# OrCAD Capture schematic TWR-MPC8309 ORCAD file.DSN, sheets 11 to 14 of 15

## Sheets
11 P10:PCI Interface & Mini PCI: size C; title: PCI Interface and Mini PCI Connector
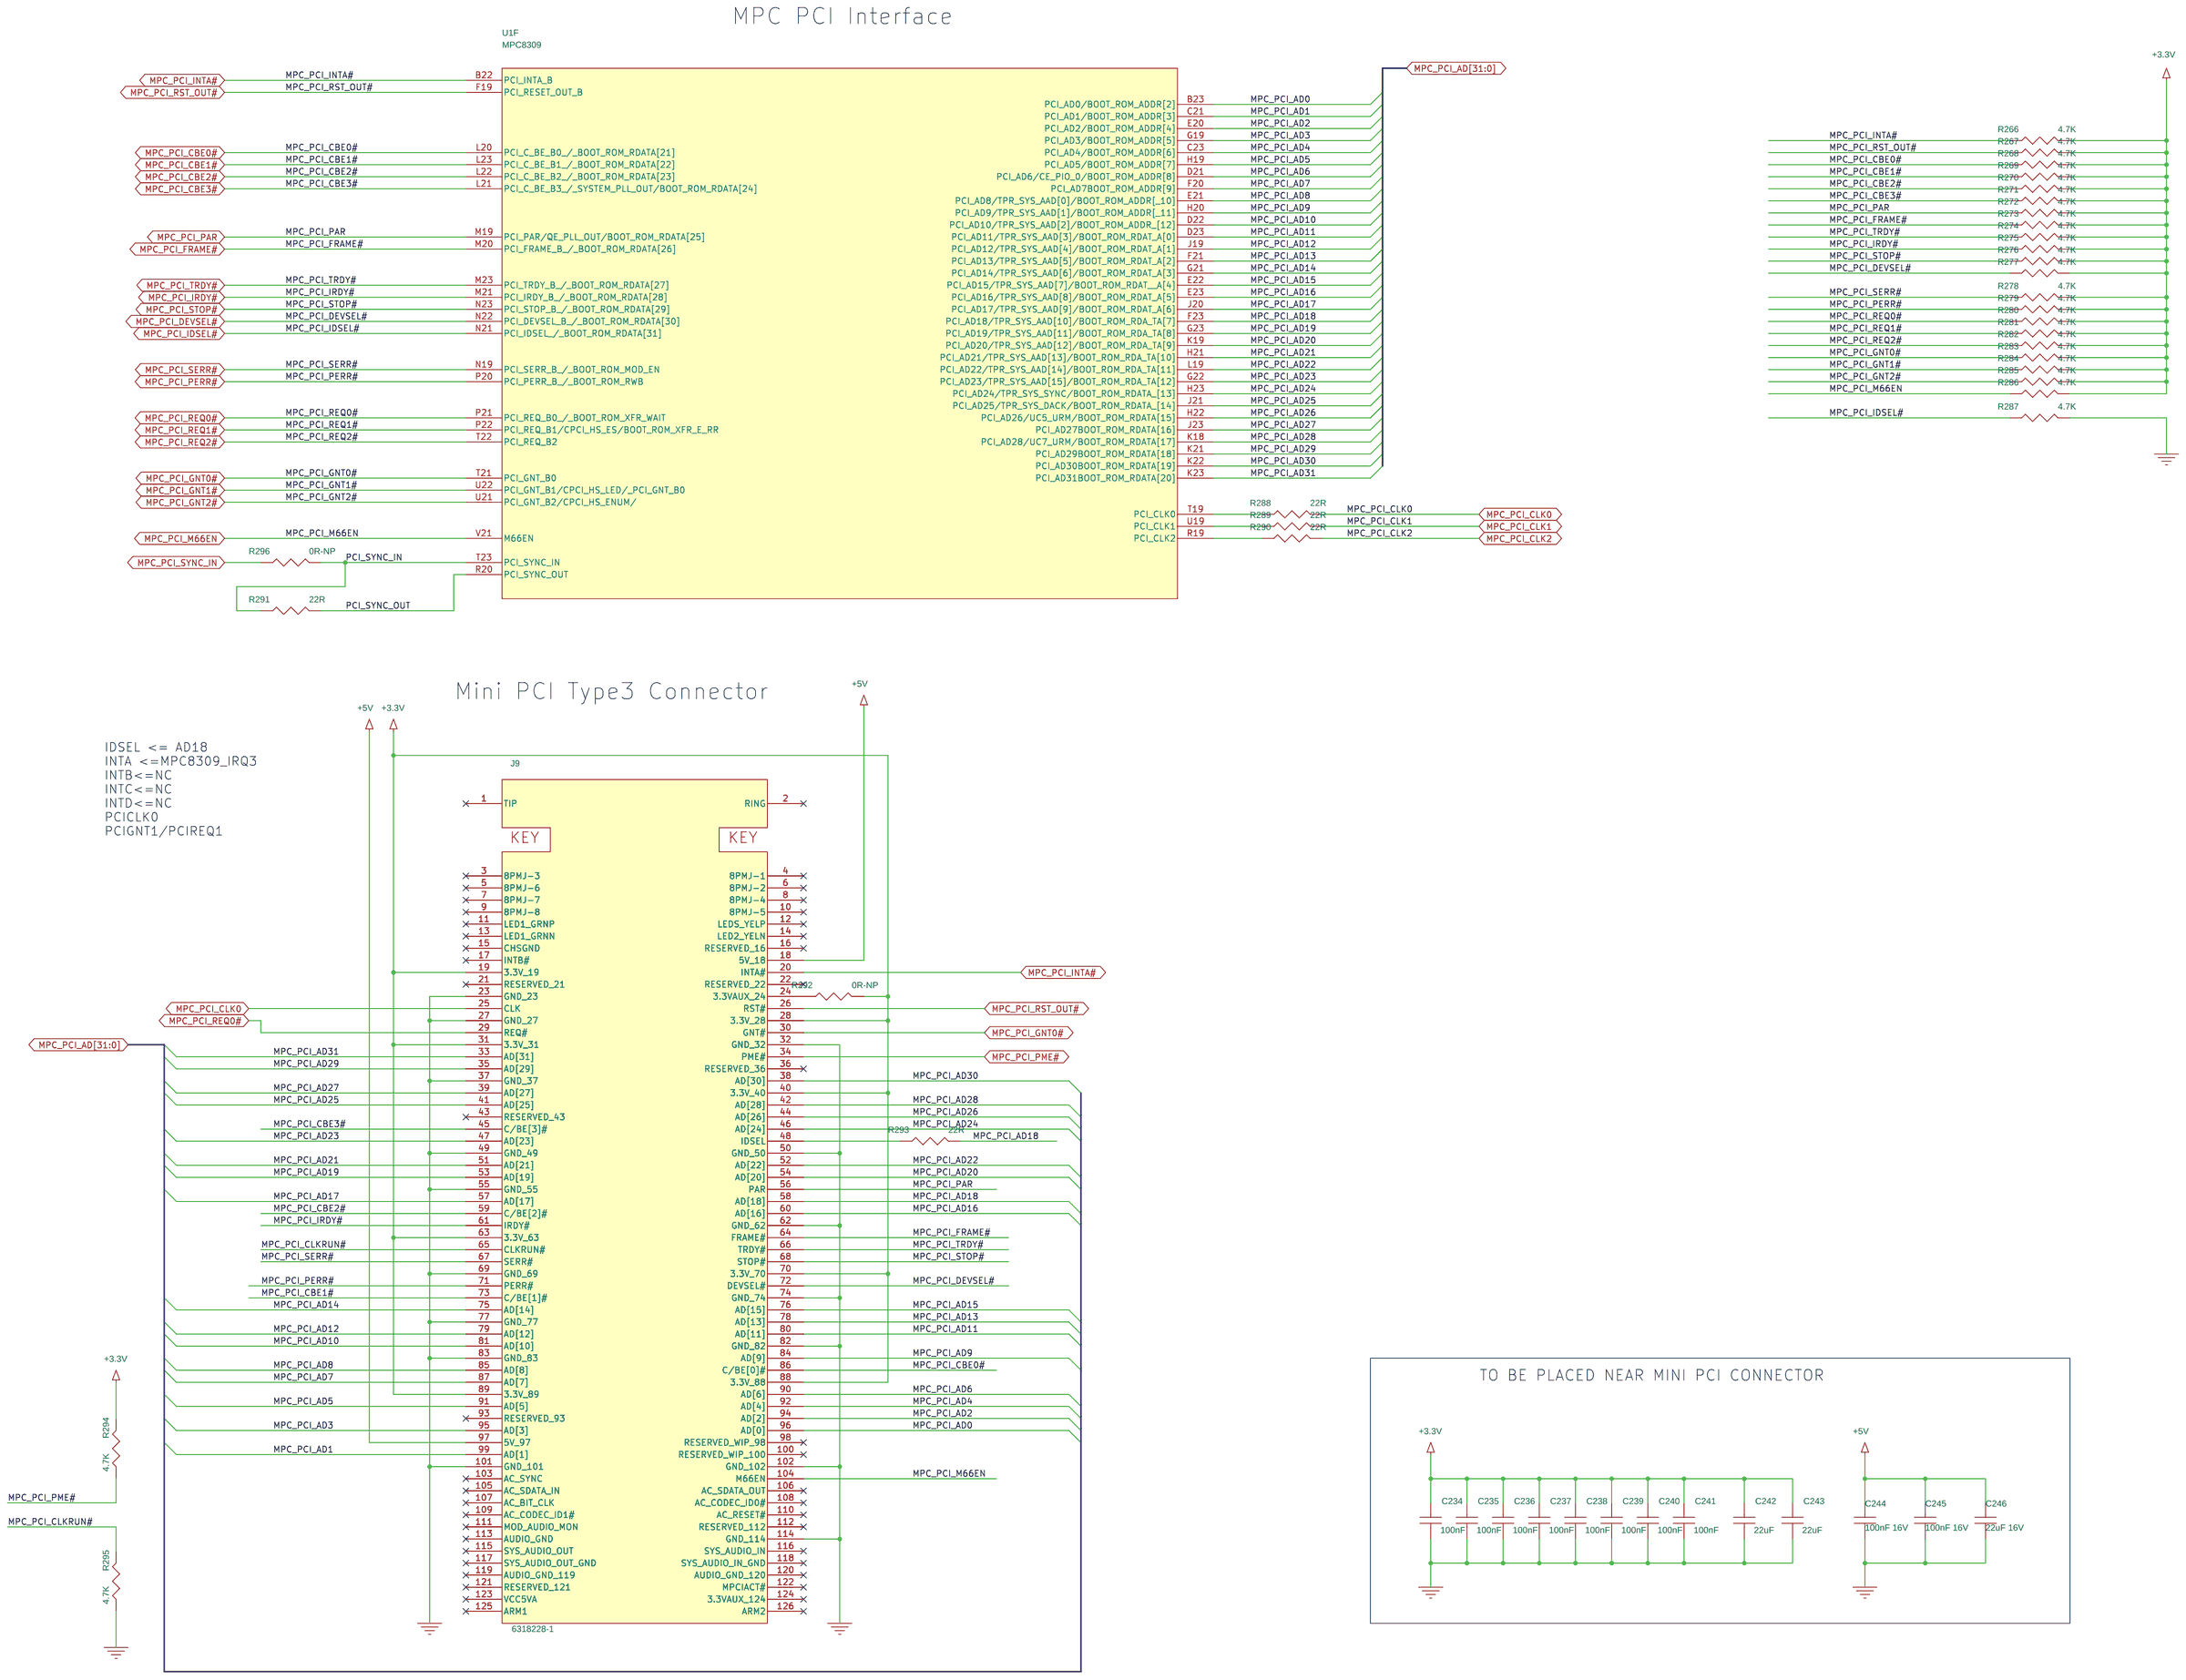
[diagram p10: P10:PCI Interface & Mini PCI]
12 P09:RS485, RS232 & RS232 MUX: size C; title: RS485, RS232 and RS232 MUX
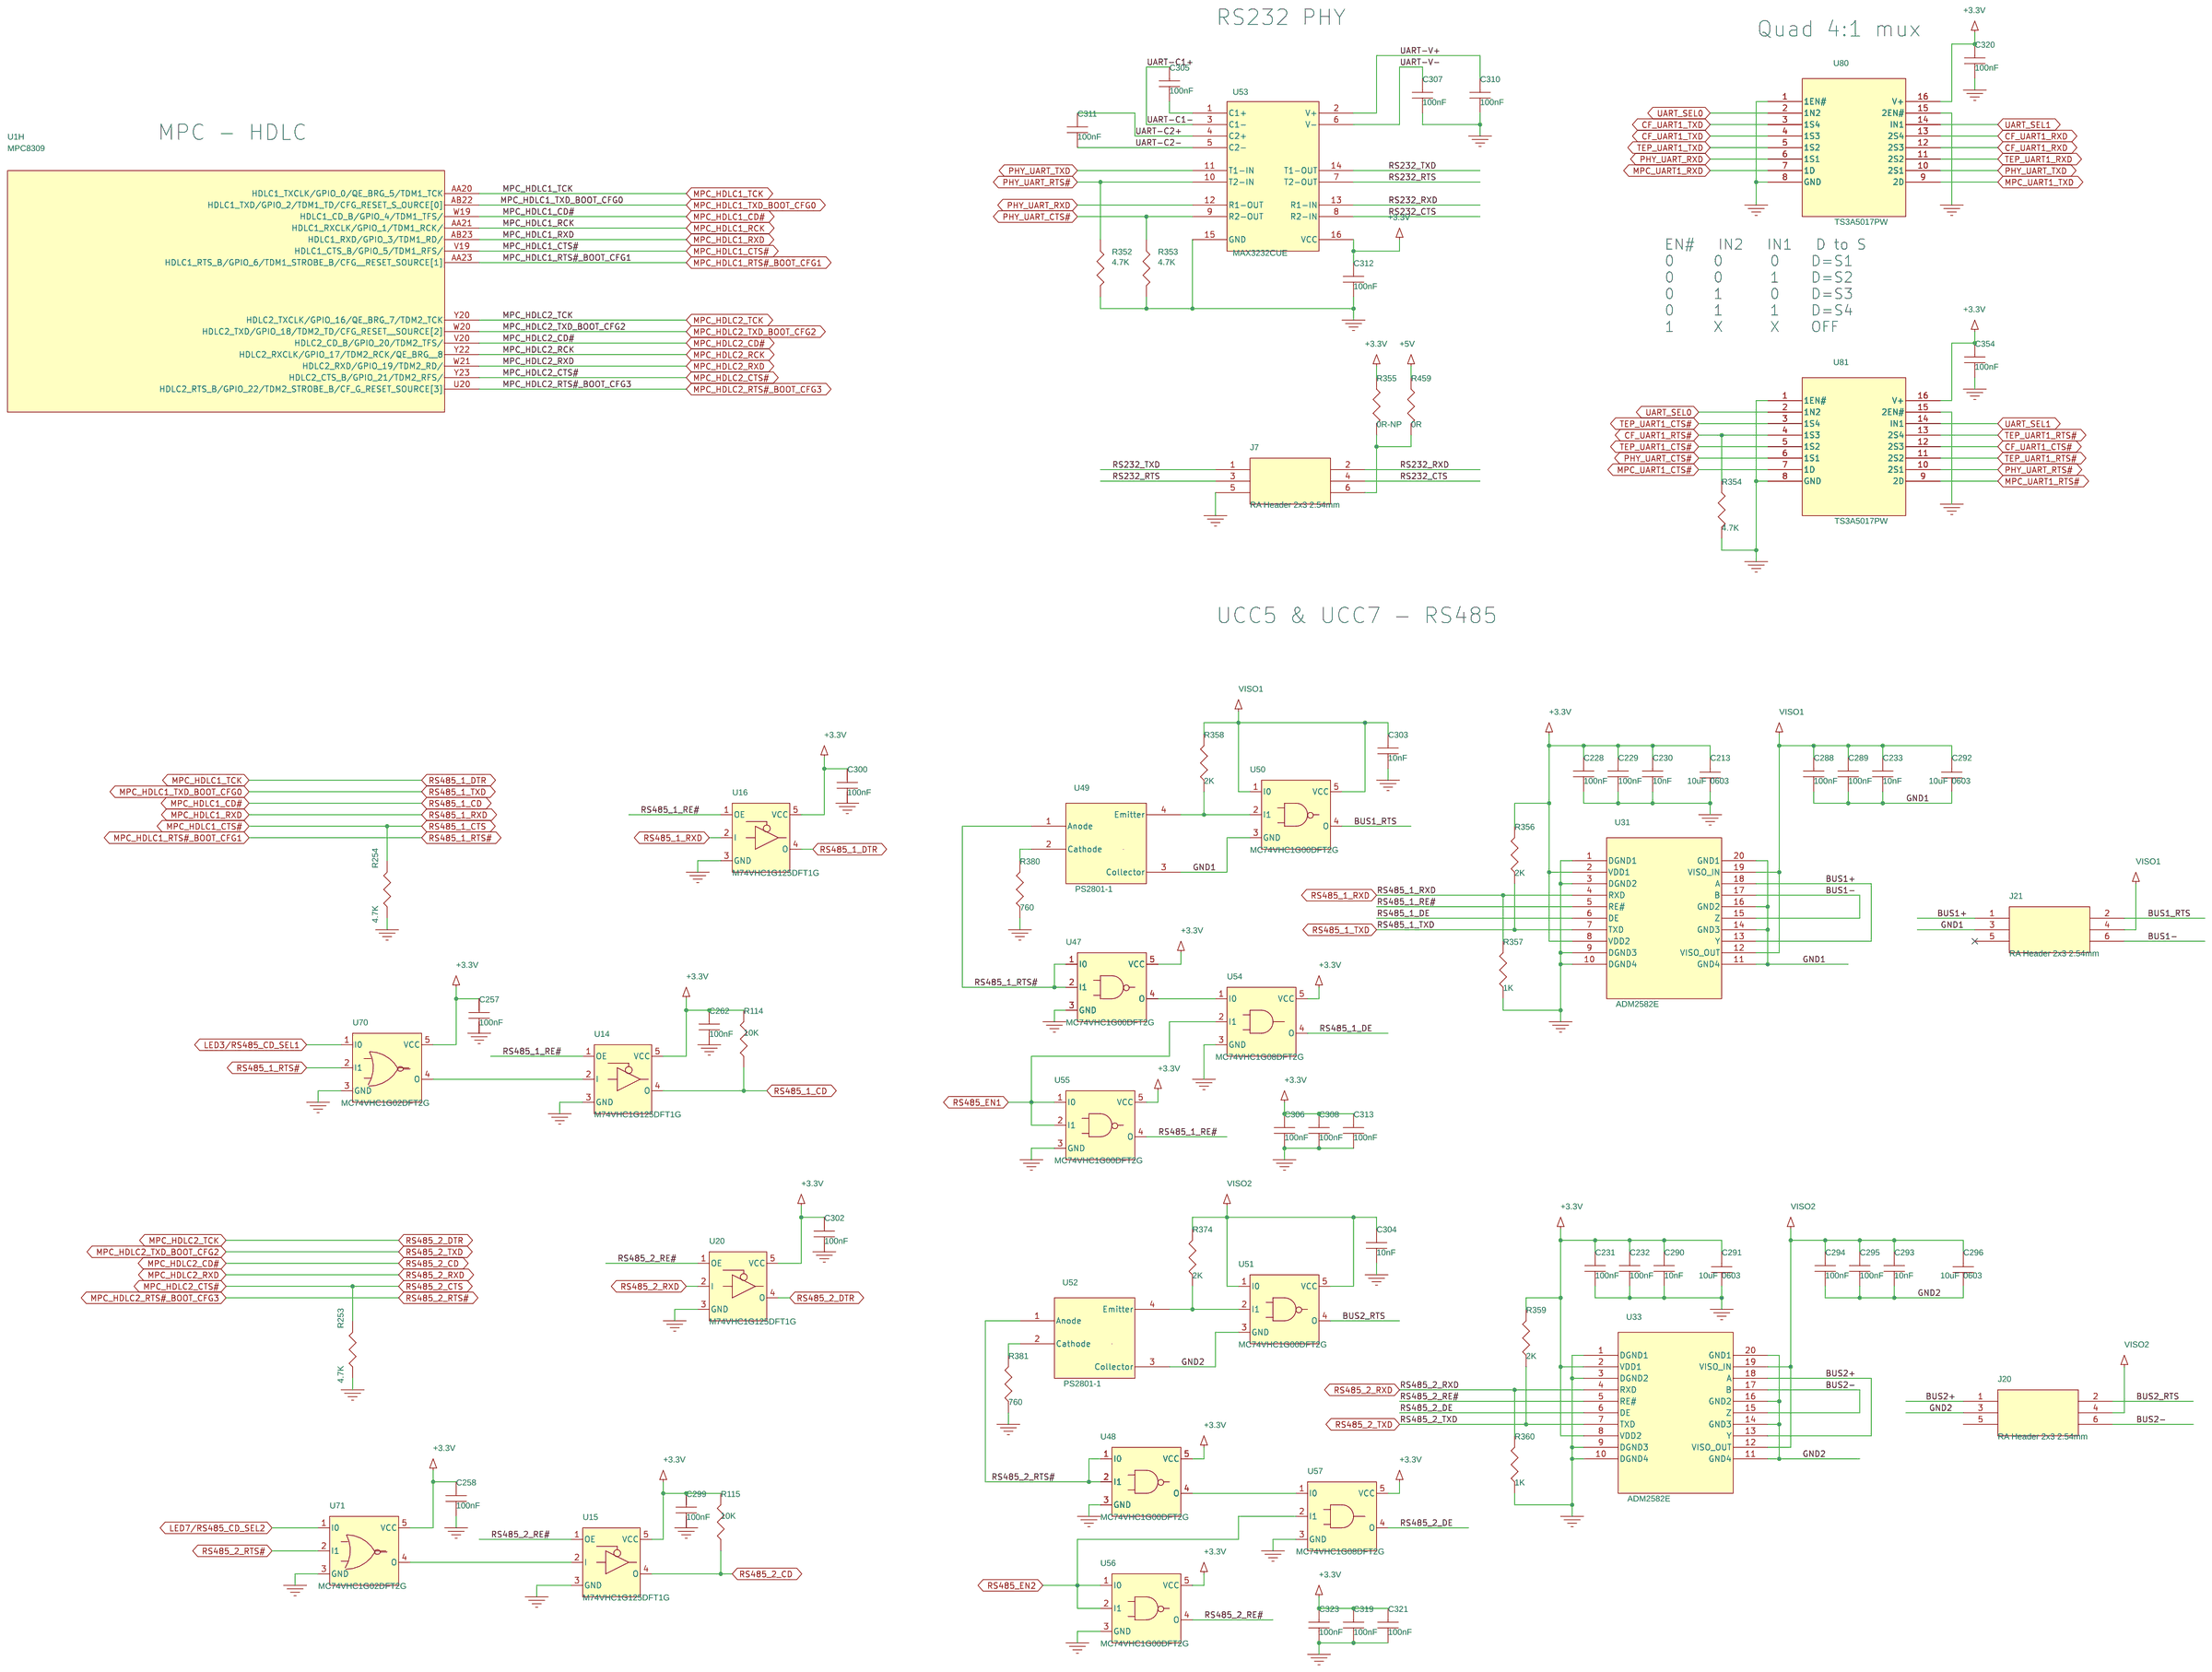
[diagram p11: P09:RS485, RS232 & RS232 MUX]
13 P04:eLBC, Latch, Buf and Logics: size C; title: eLBC, Latch, Buffer and Logics
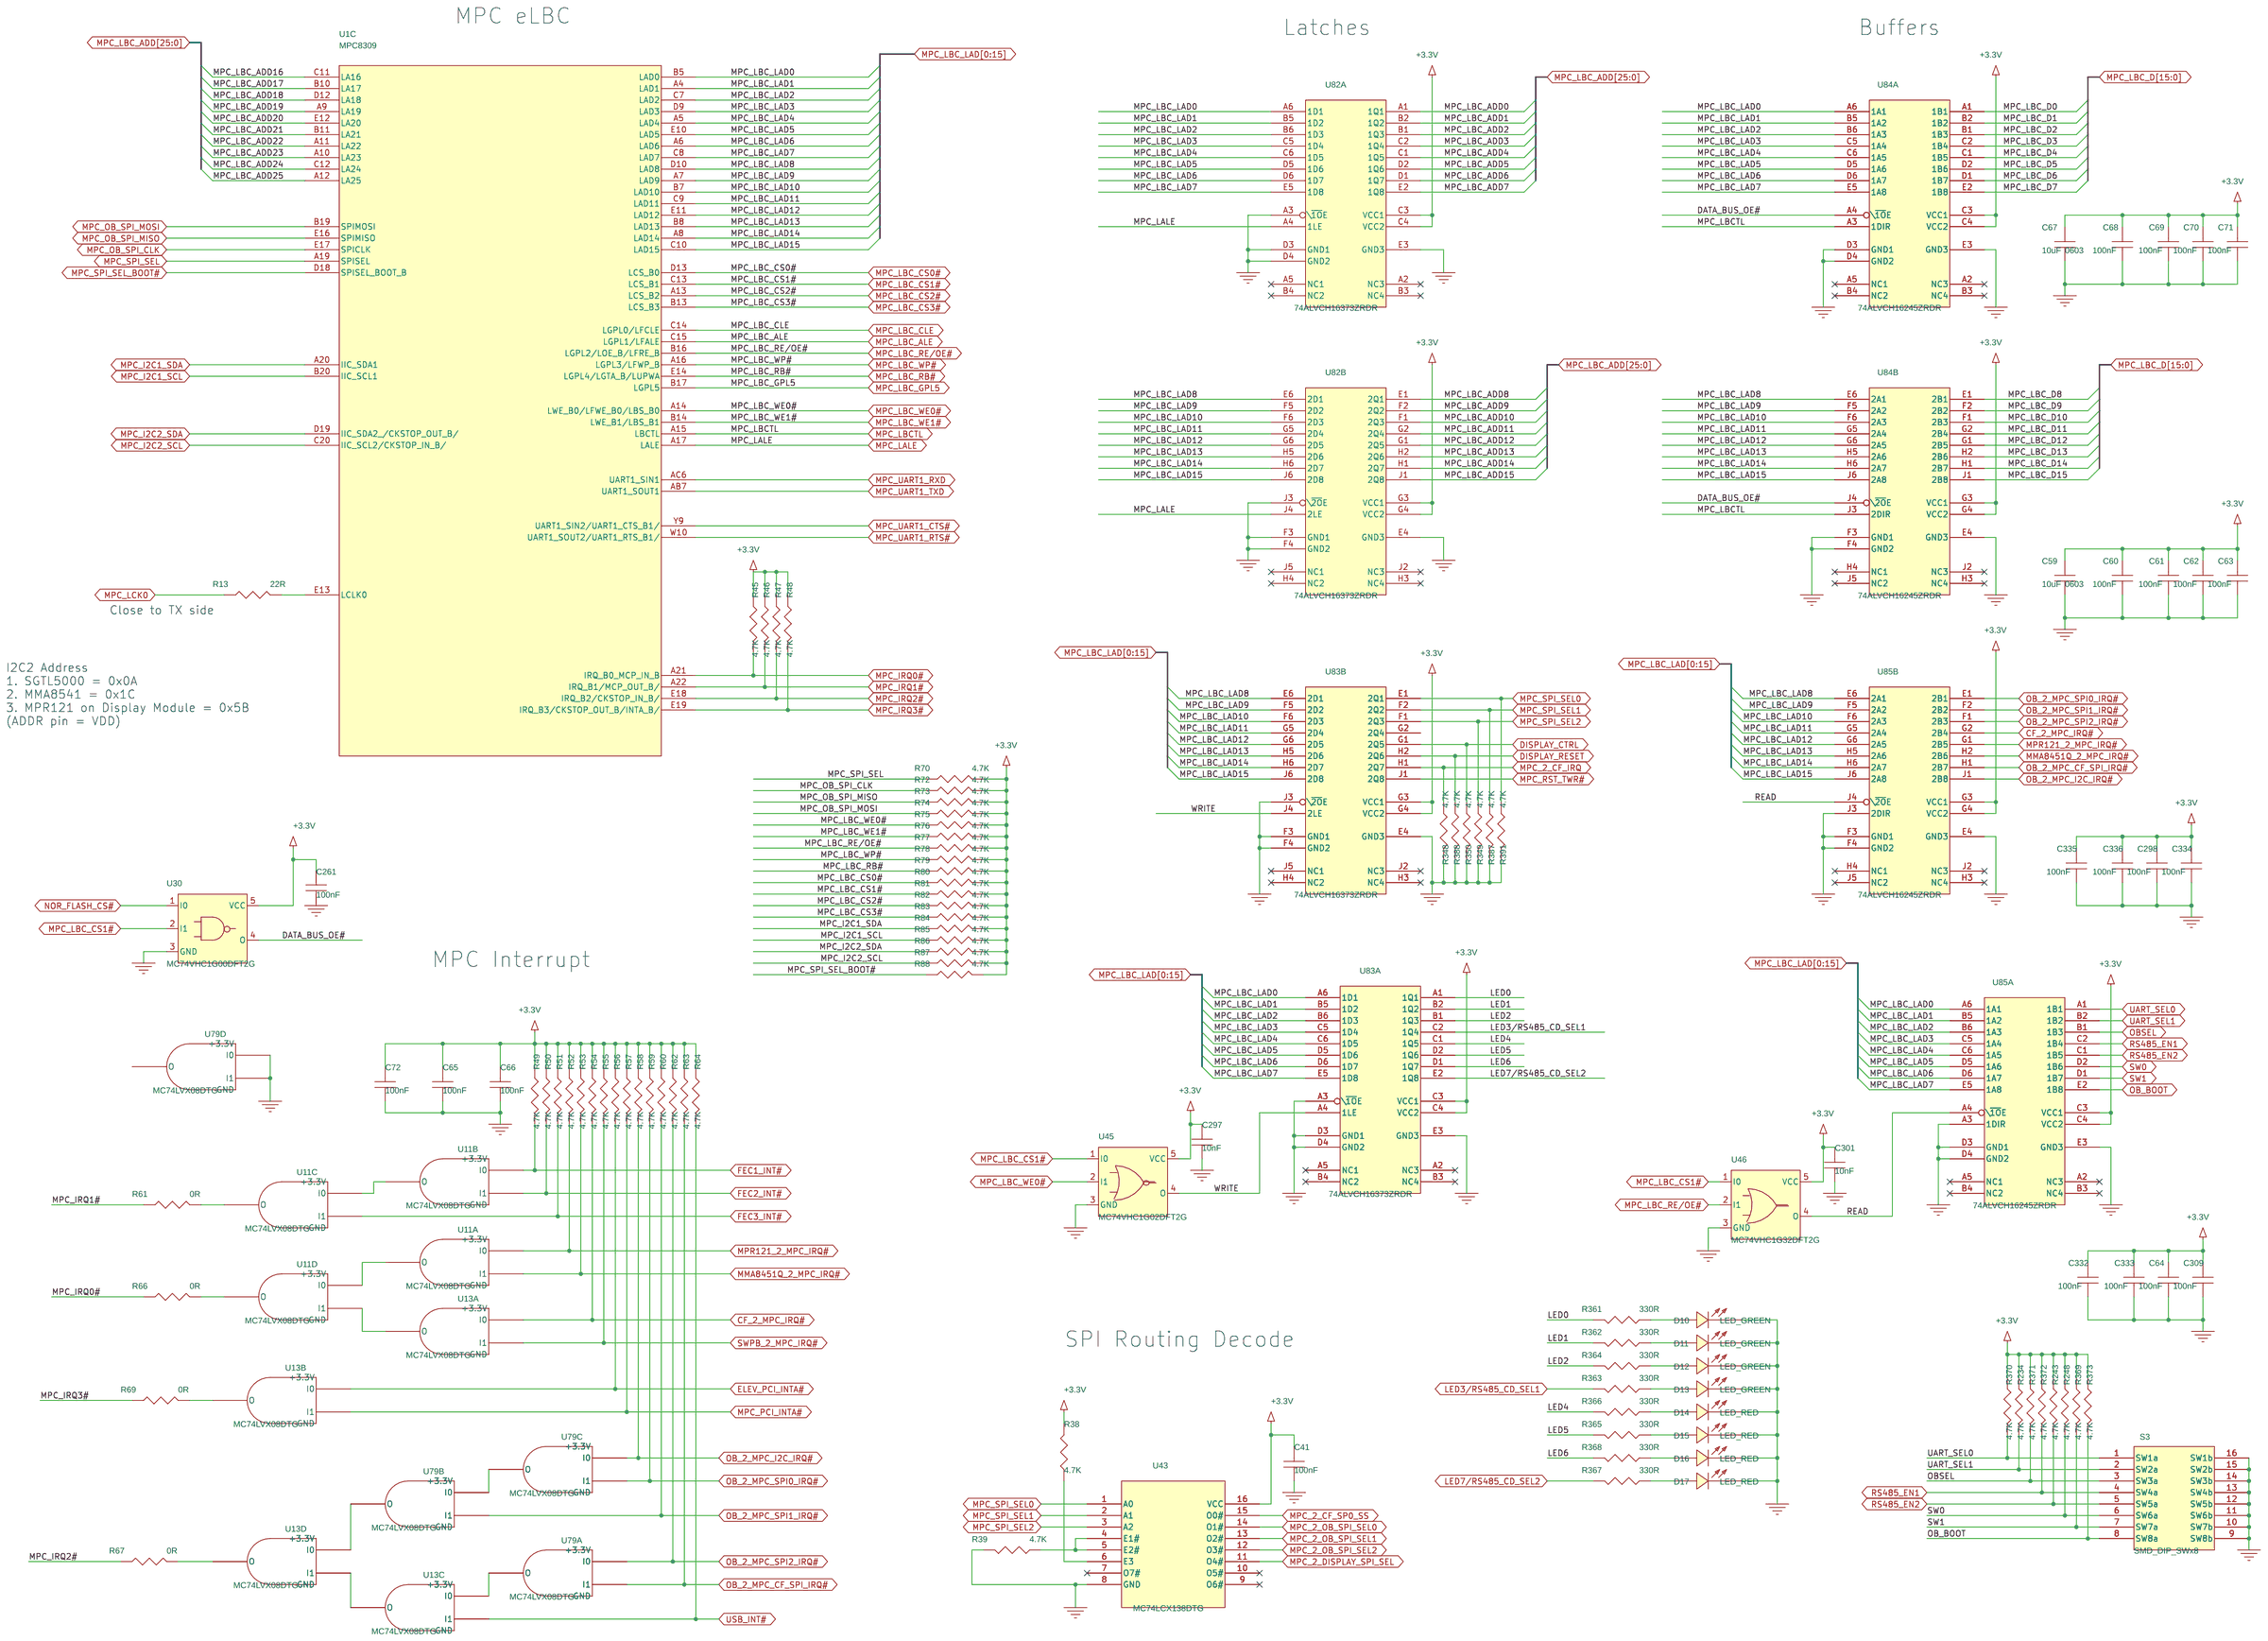
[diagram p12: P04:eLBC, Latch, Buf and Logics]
14 P06:Ethernet Interface & Clock: size C; title: Ethernet Interface and Clock
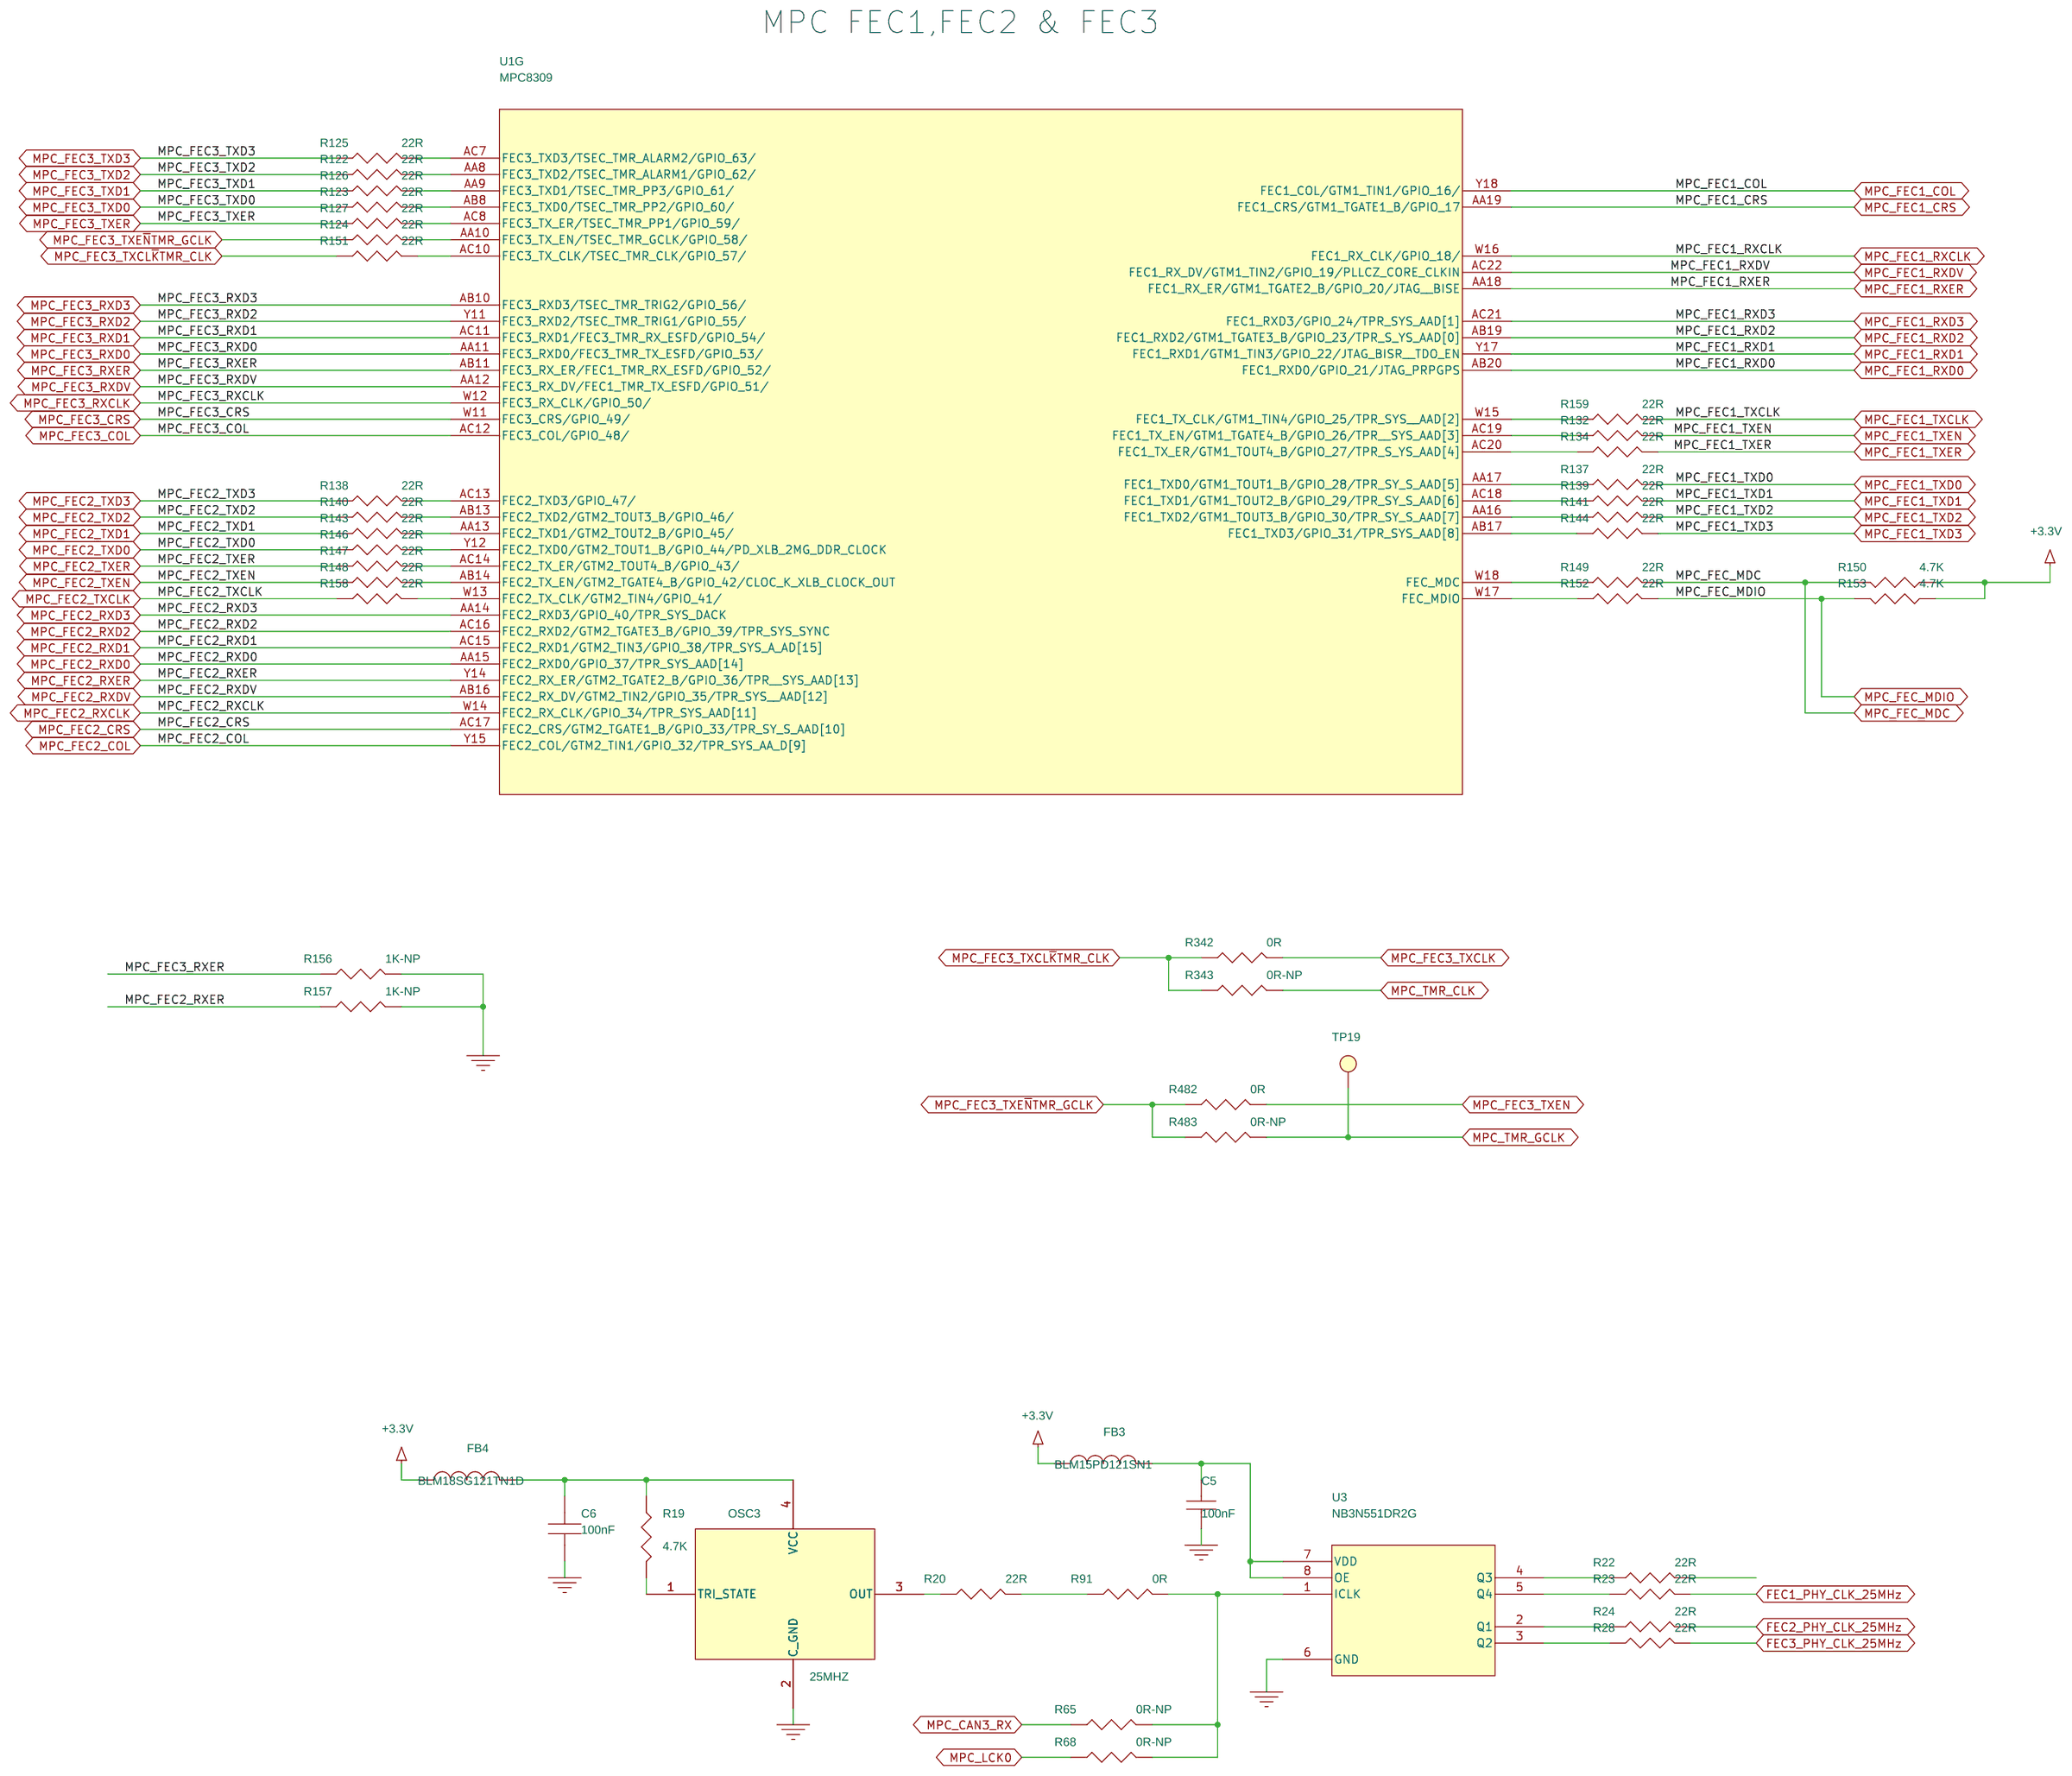
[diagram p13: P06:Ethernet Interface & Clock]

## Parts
sheet P04:eLBC, Latch, Buf and Logics
C41  100nF  [CC0402_CR]
C59  10uF  [CC0603]
C60  100nF  [CC0402_CR]
C61  100nF  [CC0402_CR]
C62  100nF  [CC0402_CR]
C63  100nF  [CC0402_CR]
C64  100nF  [CC0402_CR]
C65  100nF  [CC0402_CR]
C66  100nF  [CC0402_CR]
C67  10uF  [CC0603]
C68  100nF  [CC0402_CR]
C69  100nF  [CC0402_CR]
C70  100nF  [CC0402_CR]
C71  100nF  [CC0402_CR]
C72  100nF  [CC0402_CR]
C261  100nF  [CC0402_CR]
C297  10nF  [CC0402_CR]
C298  100nF  [CC0402_CR]
C301  10nF  [CC0402_CR]
C309  100nF  [CC0402_CR]
C332  100nF  [CC0402_CR]
C333  100nF  [CC0402_CR]
C334  100nF  [CC0402_CR]
C335  100nF  [CC0402_CR]
C336  100nF  [CC0402_CR]
D10  LED_GREEN  [LED0603]
D11  LED_GREEN  [LED0603]
D12  LED_GREEN  [LED0603]
D13  LED_GREEN  [LED0603]
D14  LED_RED  [LED0603]
D15  LED_RED  [LED0603]
D16  LED_RED  [LED0603]
D17  LED_RED  [LED0603]
R13  22R  [R0402_CR]
R38  4.7K  [R0402_CR]
R39  4.7K  [R0402_CR]
R45  4.7K  [R0402_CR]
R46  4.7K  [R0402_CR]
R47  4.7K  [R0402_CR]
R48  4.7K  [R0402_CR]
R49  4.7K  [R0402_CR]
R50  4.7K  [R0402_CR]
R51  4.7K  [R0402_CR]
R52  4.7K  [R0402_CR]
R53  4.7K  [R0402_CR]
R54  4.7K  [R0402_CR]
R55  4.7K  [R0402_CR]
R56  4.7K  [R0402_CR]
R57  4.7K  [R0402_CR]
R58  4.7K  [R0402_CR]
R59  4.7K  [R0402_CR]
R60  4.7K  [R0402_CR]
R61  0R  [R0402_CR]
R62  4.7K  [R0402_CR]
R63  4.7K  [R0402_CR]
R64  4.7K  [R0402_CR]
R66  0R  [R0402_CR]
R67  0R  [R0402_CR]
R69  0R  [R0402_CR]
R70  4.7K  [R0402_CR]
R72  4.7K  [R0402_CR]
R73  4.7K  [R0402_CR]
R74  4.7K  [R0402_CR]
R75  4.7K  [R0402_CR]
R76  4.7K  [R0402_CR]
R77  4.7K  [R0402_CR]
R78  4.7K  [R0402_CR]
R79  4.7K  [R0402_CR]
R80  4.7K  [R0402_CR]
R81  4.7K  [R0402_CR]
R82  4.7K  [R0402_CR]
R83  4.7K  [R0402_CR]
R84  4.7K  [R0402_CR]
R85  4.7K  [R0402_CR]
R86  4.7K  [R0402_CR]
R87  4.7K  [R0402_CR]
R88  4.7K  [R0402_CR]
R234  4.7K  [R0402_CR]
R243  4.7K  [R0402_CR]
R248  4.7K  [R0402_CR]
R348  4.7K  [R0402_CR]
R349  4.7K  [R0402_CR]
R350  4.7K  [R0402_CR]
R361  330R  [R0402_CR]
R362  330R  [R0402_CR]
R363  330R  [R0402_CR]
R364  330R  [R0402_CR]
R365  330R  [R0402_CR]
R366  330R  [R0402_CR]
R367  330R  [R0402_CR]
R368  330R  [R0402_CR]
R369  4.7K  [R0402_CR]
R370  4.7K  [R0402_CR]
R371  4.7K  [R0402_CR]
R372  4.7K  [R0402_CR]
R373  4.7K  [R0402_CR]
R387  4.7K  [R0402_CR]
R388  4.7K  [R0402_CR]
R391  4.7K  [R0402_CR]
S3  SMD_DIP_SWx8  [SMD_SW_8P_NHDS8]
U11  MC74LVX08DTG  [TSSOP14]  (sections A,B,C,D)
U13  MC74LVX08DTG  [TSSOP14]  (sections A,B,C,D)
U30  MC74VHC1G00DFT2G  [SOT353]
U43  MC74LCX138DTG  [TSSOP16]
U45  MC74VHC1G02DFT2G  [SOT353]
U46  MC74VHC1G32DFT2G  [SOT353]
U79  MC74LVX08DTG  [TSSOP14]  (sections A,B,C,D)
U82  74ALVCH16373ZRDR  [FBGA54]  (sections A,B)
U83  74ALVCH16373ZRDR  [FBGA54]  (sections A,B)
U84  74ALVCH16245ZRDR  [FBGA54]  (sections A,B)
U85  74ALVCH16245ZRDR  [FBGA54]  (sections A,B)
sheet P06:Ethernet Interface & Clock
C5  100nF  [CC0402_CR]
C6  100nF  [CC0402_CR]
FB3  BLM15PD121SN1  [L0402]
FB4  BLM18SG121TN1D  [L0603]
OSC3  25MHZ  [C30H]
R19  4.7K  [R0402_CR]
R20  22R  [R0402_CR]
R22  22R  [R0402_CR]
R23  22R  [R0402_CR]
R24  22R  [R0402_CR]
R28  22R  [R0402_CR]
R65  0R-NP  [R0402_CR]
R68  0R-NP  [R0402_CR]
R91  0R  [R0402_CR]
R122  22R  [R0402_CR]
R123  22R  [R0402_CR]
R124  22R  [R0402_CR]
R125  22R  [R0402_CR]
R126  22R  [R0402_CR]
R127  22R  [R0402_CR]
R132  22R  [R0402_CR]
R134  22R  [R0402_CR]
R137  22R  [R0402_CR]
R138  22R  [R0402_CR]
R139  22R  [R0402_CR]
R140  22R  [R0402_CR]
R141  22R  [R0402_CR]
R143  22R  [R0402_CR]
R144  22R  [R0402_CR]
R146  22R  [R0402_CR]
R147  22R  [R0402_CR]
R148  22R  [R0402_CR]
R149  22R  [R0402_CR]
R150  4.7K  [R0402_CR]
R151  22R  [R0402_CR]
R152  22R  [R0402_CR]
R153  4.7K  [R0402_CR]
R156  1K-NP  [R0402_CR]
R157  1K-NP  [R0402_CR]
R158  22R  [R0402_CR]
R159  22R  [R0402_CR]
R342  0R  [R0402_CR]
R343  0R-NP  [R0402_CR]
R482  0R  [R0402_CR]
R483  0R-NP  [R0402_CR]
TP19  TP  [SMD_TP]
U3  NB3N551DR2G  [SOIC127P600X173-8N]
sheet P09:RS485, RS232 & RS232 MUX
C213  10uF  [CC0603]
C228  100nF  [CC0402_CR]
C229  100nF  [CC0402_CR]
C230  10nF  [CC0402_CR]
C231  100nF  [CC0402_CR]
C232  100nF  [CC0402_CR]
C233  10nF  [CC0402_CR]
C257  100nF  [CC0402_CR]
C258  100nF  [CC0402_CR]
C262  100nF  [CC0402_CR]
C288  100nF  [CC0402_CR]
C289  100nF  [CC0402_CR]
C290  10nF  [CC0402_CR]
C291  10uF  [CC0603]
C292  10uF  [CC0603]
C293  10nF  [CC0402_CR]
C294  100nF  [CC0402_CR]
C295  100nF  [CC0402_CR]
C296  10uF  [CC0603]
C299  100nF  [CC0402_CR]
C300  100nF  [CC0402_CR]
C302  100nF  [CC0402_CR]
C303  10nF  [CC0402_CR]
C304  10nF  [CC0402_CR]
C305  100nF  [CC0603]
C306  100nF  [CC0402_CR]
C307  100nF  [CC0603]
C308  100nF  [CC0402_CR]
C310  100nF  [CC0603]
C311  100nF  [CC0603]
C312  100nF  [CC0603]
C313  100nF  [CC0402_CR]
C319  100nF  [CC0402_CR]
C320  100nF  [CC0603]
C321  100nF  [CC0402_CR]
C323  100nF  [CC0402_CR]
C354  100nF  [CC0603]
J7  RA Header 2x3 2.54mm  [header100_smd2x3_ra]
J20  RA Header 2x3 2.54mm  [header100_smd2x3_ra]
J21  RA Header 2x3 2.54mm  [header100_smd2x3_ra]
R114  10K  [R0402_CR]
R115  10K  [R0402_CR]
R253  4.7K  [R0402_CR]
R254  4.7K  [R0402_CR]
R352  4.7K  [R0402_CR]
R353  4.7K  [R0402_CR]
R354  4.7K  [R0402_CR]
R355  0R-NP  [R0603B]
R356  2K  [R0402_CR]
R357  1K  [R0402_CR]
R358  2K  [R0402_CR]
R359  2K  [R0402_CR]
R360  1K  [R0402_CR]
R374  2K  [R0402_CR]
R380  760  [R0402_CR]
R381  760  [R0402_CR]
R459  0R  [R0603B]
U14  M74VHC1G125DFT1G  [SOT353]
U15  M74VHC1G125DFT1G  [SOT353]
U16  M74VHC1G125DFT1G  [SOT353]
U20  M74VHC1G125DFT1G  [SOT353]
U31  ADM2582E  [SOIC-W20]
U33  ADM2582E  [SOIC-W20]
U47  MC74VHC1G00DFT2G  [SOT353]
U48  MC74VHC1G00DFT2G  [SOT353]
U49  PS2801-1  [SSOP4]
U50  MC74VHC1G00DFT2G  [SOT353]
U51  MC74VHC1G00DFT2G  [SOT353]
U52  PS2801-1  [SSOP4]
U53  MAX3232CUE  [SSOP16A]
U54  MC74VHC1G08DFT2G  [SOT353]
U55  MC74VHC1G00DFT2G  [SOT353]
U56  MC74VHC1G00DFT2G  [SOT353]
U57  MC74VHC1G08DFT2G  [SOT353]
U70  MC74VHC1G02DFT2G  [SOT353]
U71  MC74VHC1G02DFT2G  [SOT353]
U80  TS3A5017PW  [TSSOP16]
U81  TS3A5017PW  [TSSOP16]
sheet P10:PCI Interface & Mini PCI
C234  100nF  [CC0402_CR]
C235  100nF  [CC0402_CR]
C236  100nF  [CC0402_CR]
C237  100nF  [CC0402_CR]
C238  100nF  [CC0402_CR]
C239  100nF  [CC0402_CR]
C240  100nF  [CC0402_CR]
C241  100nF  [CC0402_CR]
C242  22uF  [CC0805]
C243  22uF  [CC0805]
C244  100nF 16V  [CC0402_CR]
C245  100nF 16V  [CC0402_CR]
C246  22uF 16V  [CC0805]
J9  6318228-1  [mini_pci_type3]
R266  4.7K  [R0402_CR]
R267  4.7K  [R0402_CR]
R268  4.7K  [R0402_CR]
R269  4.7K  [R0402_CR]
R270  4.7K  [R0402_CR]
R271  4.7K  [R0402_CR]
R272  4.7K  [R0402_CR]
R273  4.7K  [R0402_CR]
R274  4.7K  [R0402_CR]
R275  4.7K  [R0402_CR]
R276  4.7K  [R0402_CR]
R277  4.7K  [R0402_CR]
R278  4.7K  [R0402_CR]
R279  4.7K  [R0402_CR]
R280  4.7K  [R0402_CR]
R281  4.7K  [R0402_CR]
R282  4.7K  [R0402_CR]
R283  4.7K  [R0402_CR]
R284  4.7K  [R0402_CR]
R285  4.7K  [R0402_CR]
R286  4.7K  [R0402_CR]
R287  4.7K  [R0402_CR]
R288  22R  [R0402_CR]
R289  22R  [R0402_CR]
R290  22R  [R0402_CR]
R291  22R  [R0402_CR]
R292  0R-NP  [R0402_CR]
R293  22R  [R0402_CR]
R294  4.7K  [R0402_CR]
R295  4.7K  [R0402_CR]
R296  0R-NP  [R0402_CR]
sheet P14:MPC Decoupling
U1  MPC8309  [MAPBGA489_80p]  (sections A,B,C,D,E,F,G,H,I)

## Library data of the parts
C5 C41 C60-C66 C68-C72 C297 C298 C301 C309 C332-C336 = CAP_NP: Mfg: Kemet; Mfg Part#: C0402C104K8PACTU; Oper. Temp. Range: -55°C ~ 85°C; Package: 0402; Price @ 100 pcs: 0.014; Price @ 10K: 0.0060; Price @ 1K: 0.0066; RoHS Compliant?: Yes; Specifications: CAP .10UF 10V CERAMIC X5R 0402; Vendor: Digikey; Vendor Part#: 399-3027-1-ND
C59 C67 C213 C291 C292 C296 = CAP_NP: Mfg: Kemet; Mfg Part#: C0603C106M9PACTU; Oper. Temp. Range: -55°C ~ 85°C; Package: 0603; Price @ 100 pcs: 0.312; Price @ 10K: 0.105; Price @ 1K: 0.1248; RoHS Compliant?: Yes; Specifications: CAP CER 10UF 6.3V X5R 0603; Vendor: Digikey; Vendor Part#: 399-5504-1-ND
C228-C241 C244 C245 C257 C258 C261 C262 C288-C290 C293-C295 C299 C300 C302-C304 C306 C308 C313 C319 C321 C323 = CAP_NP: Mfg: Kemet; Mfg Part#: C0402C104K8PACTU; Package: 0402; RoHS Compliant?: Yes; Specifications: CAP .10UF 10V CERAMIC X5R 0402
D10-D17 = LED: Mfg: Lumex; Mfg Part#: SML-LX0603GW-TR; Package: 0603; RoHS Compliant?: Yes; Specifications: LED 565NM GRN DIFF 0603 SMD
R13 R20 R65 R68 R91 R288-R291 = RESISTOR: Mfg: Yageo; Mfg Part#: RC0402FR-0722RL; Oper. Temp. Range: -55°C ~ 85°C; Package: 0402; Price @ 100 pcs: 0.066; Price @ 10K: 0.036; Price @ 1K: 0.00243; RoHS Compliant?: Yes; Specifications: RES 22.0 OHM 1/16W 1% 0402 SMD; Vendor: Digikey; Vendor Part#: 311-22.0LRCT-ND
R38 R39 = RESISTOR: Mfg: Yageo; Mfg Part#: RC0402JR-0710KL; Oper. Temp. Range: -55°C ~ 85°C; Package: 0402; Price @ 100 pcs: 0.066; Price @ 10K: 0.00213; Price @ 1K: 0.035; RoHS Compliant?: Yes; Specifications: RES 10K OHM 1/16W 5% 0402 SMD; Vendor: Digikey; Vendor Part#: 311-10KJRCT-ND
R45-R60 R62-R64 R70 R72-R88 R150 R153 R234 R243 R248 R253 R254 R266-R287 R348-R350 R369-R373 R387 R388 R391 = RESISTOR: Mfg: Yageo; Mfg Part#: RC0402JR-074K7L; Oper. Temp. Range: -55°C ~ 85°C; Package: 0402; Price @ 100 pcs: 0.0066; Price @ 10K: 0.00213; Price @ 1K: 0.035; RoHS Compliant?: Yes; Specifications: RES 4.7K OHM 1/16W 5% 0402 SMD; Vendor: Digikey; Vendor Part#: 311-4.7KJRCT-ND
R61 R66 R67 R69 = R_4: RES MF ZERO OHM 1/10W -- 0603; AGILE_PN: 470-75407; CAD_APPROVED: Yes; CLASS: Discrete; MFG_NAME01: THYE MING TECH CO LTD; MFG_PN01: CR-03JL7----0R; ROHS: Yes; Tolerance: 1%
R361-R368 = Res: Res, 100K, 1%, Chip, 0.063W, SMD, Size 0402; FPLIST: R0402; GDA Part No: GRX-R-00000037; Mfg: KOA; Mfg Part No: RK73H1ETTP1003F; Part Number: GRX-R-00000037; ROOM: POWER; Sub_Type: Chip; Tolerance: 1%
S3 = SMD_DIP_SW8
U11 U13 U79 = 74LVX08_2: IC GATE AND QUAD 2-INPUT 2-3.6V TSSOP14; AGILE_PN: 312-79611; CAD_APPROVED: Yes; CLASS: IC; HEIGHT: 1.2 MM; MFG_NAME01: ON SEMICONDUCTOR; ROHS: Yes
U30 U47 U48 U50 U51 U55 U56 = 74VHC1G00: Mfg: ON Semi; RoHS Compliant?: Yes; Specifications: IC GATE NAND SGL 2INPUT SOT353
U43 = MC74LCX138DTG
U45 U70 U71 = 74VHC1G02_1: CLASS: IC
U46 = 74VHC1G32: CLASS: IC
U82 U83 = 74ALVCH16373ZRD
U84 U85 = 74ALVCH16245ZRD
C6 = Cap_bulk_nonpol_1: Cap, 0.01uF, 10%, Cer-X5R, 16V, SMD, Size 0402; Material: Cer-X7R; Mfg: AVX; Mfg Part No: 0402YD103MAT2A; ROOM: ETH; Volts: 16V
FB3 FB4 = INDUCTOR_0: Ferrite Bead, 2A, 140 OHMS, 1GHZ, SMD0603; Cost_Proto: 0.25; Cost_Vol: 0.14; Mfg: Murata; Mfg Part No: BLM18EG101TN1; Room: ETH
OSC3 = Osc_EC2600TS-33.333M: ITTI,OSC, C30H25-50.000-12, 3.3V, SMD; Mfg: ITTI; Mfg Part No: C30H25-50.000-12; ROOM: ETH
R19 = Res: Res, 4.7K, 5%, Chip, 0.063W, SMD, Size 0402; GDA Part No: GRX-R-00000587; Mfg: KOA; Mfg Part No: RK73B1ETTP472J; Part Number: GRX-R-00000587; ROOM: ETH; Sub_Type: Chip; Tolerance: 5%
R22-R24 R28 R122-R127 R132 R134 R137-R141 R143 R144 R146-R149 R151 R152 R158 R159 = RESISTOR: Mfg: Yageo; Mfg Part#: RC0402FR-0722RL; Package: 0402; Price @ 100 pcs: 0.066; Price @ 10K: 0.036; Price @ 1K: 0.00243; RoHS Compliant?: Yes; Specifications: RES 22.0 OHM 1/16W 1% 0402 SMD; Vendor: Digikey; Vendor Part#: 311-22.0LRCT-ND
R156 R157 = RESISTOR: Mfg: Yageo; Mfg Part#: RC0402FR-071KL; Mounting: NU; Oper. Temp. Range: -55°C ~ 85°C; Package: 0402; Price @ 100 pcs: 0.036; Price @ 10K: 0.00242; Price @ 1K: 0.0142; RoHS Compliant?: Yes; Specifications: RES 1.00K OHM 1/16W 1% 0402 SMD; Vendor: Digikey; Vendor Part#: 311-1.00KLRCT-ND
R342 R343 R356-R360 R374 R380 R381 R482 R483 = RESISTOR: Mfg: Yageo; Mfg Part#: RC0402FR-0722RL; Mounting: NU; Package: 0402; RoHS Compliant?: Yes; Specifications: RES 22.0 OHM 1/16W 1% 0402 SMD
TP19 = TP: RoHS Compliant?: Yes
U3 = IC_CLKBUF_1to_4_NB3N551: Mfg: ON Semiconductor; Vendor: MOUSER; Vendor Part#: 863-NB3N551DR2G
C305 C307 C310-C312 C320 C354 = CAP_NP_1: CLASS: Discrete
J7 J20 J21 = Conn_BDC_2x3_male_Header_0: Mfg: Samtec; Mfg Part#: TSM-103-01-L-DV; Package: SMD 100mil; Price @ 100 pcs: 0.324; Price @ 10K: 0.268; Price @ 1K: 0.324; RoHS Compliant?: Yes; Specifications: Conn Header 100mil x 100mil SMD; Vendor: Samtec; Vendor Part#: TSM-103-01-L-DV
R114 R115 = R_4: RES MF 10K 1/16W 5% 0402; AGILE_PN: 470-75557; CAD_APPROVED: Yes; CLASS: Discrete; MFG_NAME01: VISHAY INTERTECHNOLOGY; MFG_PN01: CRCW040210K0JNED; ROHS: Yes; Tolerance: 5%
R352-R354 = R_4: CLASS: Discrete
R355 R459 = R_4: ALT_SYMBOLS: R0402_CR; CLASS: Discrete
U14-U16 U20 = 74VHC1G125: IC BUF SGL TS 2-5.5V SOT-353; AGILE_PN: 312-79602; CAD_APPROVED: Yes; CLASS: IC; HEIGHT: 1.1MM; MFG_NAME01: ON SEMICONDUCTOR; ROHS: Yes
U31 U33 = ADM2582E
U49 U52 = PS2801-1
U53 = MAX3232CUE: CLASS: IC
U54 U57 = 74VHC1G08: IC GATE AND SGL 2-INPUT 2-5.5V SOT-353; AGILE_PN: 312-79604; CAD_APPROVED: Yes; CLASS: IC; HEIGHT: 1.1MM; MFG_NAME01: ON SEMICONDUCTOR; MFG_PN01: MC74VHC1G08DFT1G; ROHS: Yes
U80 U81 = TS3A5017PW
C242 C243 C246 = CAP_NP: Mfg: Taiyo Yuden; Mfg Part#: LMK212BJ226MG-T; Oper. Temp. Range: -55°C ~ 85°C; Package: 0805; RoHS Compliant?: Yes; Specifications: CAP CER 22UF 10V X5R 0805
J9 = CONN_MINIPCI_TYPE3_1: Board: MPC8309; Mfg: Tyco Electronics; Package: SMD-124PIN CONN; RoHS Compliant?: Yes; Specifications: Connector,124 Pin Mini PCI; Vendor: Mouser
R292 R296 = RESISTOR: Mfg: Yageo; Mfg Part#: RC0402JR-070RL; Mounting: NU; Oper. Temp. Range: -55 to +125C; Package: 0402; RoHS Compliant?: Yes; Specifications: RES 0.0 OHM 1/16W 5% 0402 SMD
R293 = RESISTOR: Mfg: Yageo; Mfg Part#: RC0402FR-0722RL; Package: 0402; RoHS Compliant?: Yes; Specifications: RES 22.0 OHM 1/16W 1% 0402 SMD
R294 R295 = RESISTOR: Mfg: Yageo; Mfg Part#: RC0402JR-074K7L; Package: 0402; RoHS Compliant?: Yes; Specifications: RES 4.7K OHM 1/16W 5% 0402 SMD
U1 = IC_CPU_MPC8309_1: Mfg: Freescale; Mfg Part#: MPC8309CVMAFDCA; Package: MAPBGA; Price @ 100 pcs: 10; Price @ 10K: 10; Price @ 1K: 10; RoHS Compliant?: Yes; Specifications: PowerQUICC II Pro Integrated Communications Processor; Vendor: Freescale; Vendor Part#: MPC8309CVMAFDCA

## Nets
+3.3V: C41.2 C59.2 C60.2 C61.2 C62.2 C63.2 C64.2 C65.2 C66.2 C67.2 C68.2 C69.2 C70.2 C71.2 C72.2 C213.2 C228.1 C229.1 C230.1 C231.1 C232.1 C234.1 C235.1 C236.1 C237.1 C238.1 C239.1 C240.1 C241.1 C242.1 C243.1 C257.1 C258.1 C261.1 C262.1 C290.1 C291.2 C297.2 C298.2 C299.1 C300.1 C301.2 C302.1 C306.1 C308.1 C309.2 C312.1 C313.1 C319.1 C320.1 C321.1 C323.1 C332.2 C333.2 C334.2 C335.2 C336.2 C354.1 FB3.2 FB4.2 J9.19(3.3V) J9.28(3.3V) J9.31(3.3V) J9.40(3.3V) J9.63(3.3V) J9.70(3.3V) J9.88(3.3V) J9.89(3.3V) R38.2 R45.1 R46.1 R47.1 R48.1 R49.1 R50.1 R51.1 R52.1 R53.1 R54.1 R55.1 R56.1 R57.1 R58.1 R59.1 R60.1 R62.1 R63.1 R64.1 R70.2 R72.2 R73.2 R74.2 R75.2 R76.2 R77.2 R78.2 R79.2 R80.2 R81.2 R82.2 R83.2 R84.2 R85.2 R86.2 R87.2 R88.2 R114.1 R115.1 R150.2 R153.2 R234.1 R243.1 R248.1 R266.2 R267.2 R268.2 R269.2 R270.2 R271.2 R272.2 R273.2 R274.2 R275.2 R276.2 R277.2 R278.2 R279.2 R280.2 R281.2 R282.2 R283.2 R284.2 R285.2 R286.2 R292.2 R294.2 R355.2 R356.2 R359.2 R369.1 R370.1 R371.1 R372.1 R373.1 U11.14(+3.3V) U13.14(+3.3V) U14.5(VCC) U15.5(VCC) U16.5(VCC) U20.5(VCC) U30.5(VCC) U31.2(VDD1) U31.8(VDD2) U33.2(VDD1) U33.8(VDD2) U43.16(VCC) U45.5(VCC) U46.5(VCC) U47.5(VCC) U48.5(VCC) U53.16(VCC) U54.5(VCC) U55.5(VCC) U56.5(VCC) U57.5(VCC) U70.5(VCC) U71.5(VCC) U79.14(+3.3V) U80.16(V+) U81.16(V+) U82.C3(VCC1) U82.C4(VCC2) U82.G3(VCC1) U82.G4(VCC2) U83.C3(VCC1) U83.C4(VCC2) U83.G3(VCC1) U83.G4(VCC2) U84.C3(VCC1) U84.C4(VCC2) U84.G3(VCC1) U84.G4(VCC2) U85.C3(VCC1) U85.C4(VCC2) U85.G3(VCC1) U85.G4(VCC2) ; also on sheet 1 2 4 5 7 8 9 10 15
+5V: C244.1 C245.1 C246.1 J9.18(5V) J9.97(5V) R459.2 ; also on sheet 1 5 9 15
GND: C5.1 C6.2 C41.1 C59.1 C60.1 C61.1 C62.1 C63.1 C64.1 C65.1 C66.1 C67.1 C68.1 C69.1 C70.1 C71.1 C72.1 C213.1 C228.2 C229.2 C230.2 C231.2 C232.2 C234.2 C235.2 C236.2 C237.2 C238.2 C239.2 C240.2 C241.2 C242.2 C243.2 C244.2 C245.2 C246.2 C257.2 C258.2 C261.2 C262.2 C290.2 C291.1 C297.1 C298.1 C299.2 C300.2 C301.1 C302.2 C303.2 C304.2 C306.2 C307.2 C308.2 C309.1 C310.2 C312.2 C313.2 C319.2 C320.2 C321.2 C323.2 C332.1 C333.1 C334.1 C335.1 C336.1 C354.2 D10.2(CATHODE) D11.2(CATHODE) D12.2(CATHODE) D13.2(CATHODE) D14.2(CATHODE) D15.2(CATHODE) D16.2(CATHODE) D17.2(CATHODE) J7.5 J9.23(GND) J9.27(GND) J9.32(GND) J9.37(GND) J9.49(GND) J9.50(GND) J9.55(GND) J9.62(GND) J9.69(GND) J9.74(GND) J9.77(GND) J9.82(GND) J9.83(GND) J9.101(GND) J9.102(GND) J9.114(GND) OSC3.2(C_GND) R39.2 R156.2 R157.2 R253.2 R254.2 R287.2 R295.1 R348.1 R349.1 R350.1 R352.1 R353.1 R354.1 R357.1 R360.1 R380.1 R381.1 R387.1 R388.1 R391.1 S3.9(SW8b) S3.10(SW7b) S3.11(SW6b) S3.12(SW5b) S3.13(SW4b) S3.14(SW3b) S3.15(SW2b) S3.16(SW1b) U3.6(GND) U11.7(GND) U13.7(GND) U14.3(GND) U15.3(GND) U16.3(GND) U20.3(GND) U30.3(GND) U31.1(DGND1) U31.3(DGND2) U31.9(DGND3) U31.10(DGND4) U33.1(DGND1) U33.3(DGND2) U33.9(DGND3) U33.10(DGND4) U43.8(GND) U45.3(GND) U46.3(GND) U47.3(GND) U48.3(GND) U53.15(GND) U54.3(GND) U55.3(GND) U56.3(GND) U57.3(GND) U70.3(GND) U71.3(GND) U79.7(GND) U79.12(I0) U79.13(I1) U80.1(1EN#) U80.8(GND) U80.15(2EN#) U81.1(1EN#) U81.8(GND) U81.15(2EN#) U82.A3(\~{1O}E) U82.D3(GND1) U82.D4(GND2) U82.E3(GND3) U82.E4(GND3) U82.F3(GND1) U82.F4(GND2) U82.J3(\~{2O}E) U83.A3(\~{1O}E) U83.D3(GND1) U83.D4(GND2) U83.E3(GND3) U83.E4(GND3) U83.F3(GND1) U83.F4(GND2) U83.J3(\~{2O}E) U84.D3(GND1) U84.D4(GND2) U84.E3(GND3) U84.E4(GND3) U84.F3(GND1) U84.F4(GND2) U85.A3(1DIR) U85.D3(GND1) U85.D4(GND2) U85.E3(GND3) U85.E4(GND3) U85.F3(GND1) U85.F4(GND2) U85.J3(2DIR) ; also on sheet 1 2 4 5 6 7 8 9 10 15
GND1: C233.2 C288.2 C289.2 C292.1 J21.3 U31.11(GND4) U31.14(GND3) U31.16(GND2) U31.20(GND1) U49.3(Collector) U50.3(GND)
GND2: C293.2 C294.2 C295.2 C296.1 J20.3 U33.11(GND4) U33.14(GND3) U33.16(GND2) U33.20(GND1) U51.3(GND) U52.3(Collector)
BUS1+: J21.1 U31.13(Y) U31.18(A)
BUS1-: J21.6 U31.15(Z) U31.17(B)
BUS1_RTS: J21.2 U50.4(O)
BUS2+: J20.1 U33.13(Y) U33.18(A)
BUS2-: J20.6 U33.15(Z) U33.17(B)
BUS2_RTS: J20.2 U51.4(O)
CF_2_MPC_IRQ#: R54.2 U13.1(I0) U85.G2(2B4) ; also on sheet 15
CF_UART1_CTS#: U81.12(2S3) ; also on sheet 15
CF_UART1_RTS#: R354.2 U81.4(1S3) ; also on sheet 6 15
CF_UART1_RXD: U80.12(2S3) U80.13(2S4) ; also on sheet 15
CF_UART1_TXD: U80.3(1S4) U80.4(1S3) ; also on sheet 15
DATA_BUS_OE#: U30.4(O) U84.A4(\~{1O}E) U84.J4(\~{2O}E)
DISPLAY_CTRL: R350.2 U83.G1(2Q5) ; also on sheet 5
DISPLAY_RESET: R388.2 U83.H2(2Q6) ; also on sheet 5
ELEV_PCI_INTA#: R56.2 U13.4(I0)
FEC1_INT#: R49.2 U11.4(I0) ; also on sheet 7
FEC1_PHY_CLK_25MHz: R23.2 ; also on sheet 7
FEC2_INT#: R50.2 U11.5(I1) ; also on sheet 7
FEC2_PHY_CLK_25MHz: R24.2 ; also on sheet 7
FEC3_INT#: R51.2 U11.10(I1)
FEC3_PHY_CLK_25MHz: R28.2 ; also on sheet 6
LED0: R361.2 U83.A1(1Q1)
LED1: R362.2 U83.B2(1Q2)
LED2: R364.2 U83.B1(1Q3)
LED3/RS485_CD_SEL1: R363.2 U70.1(I0) U83.C2(1Q4)
LED4: R366.2 U83.C1(1Q5)
LED5: R365.2 U83.D2(1Q6)
LED6: R368.2 U83.D1(1Q7)
LED7/RS485_CD_SEL2: R367.2 U71.1(I0) U83.E2(1Q8)
MMA8451Q_2_MPC_IRQ#: R53.2 U11.2(I1) U85.H2(2B6) ; also on sheet 15
MPC_2_CF_IRQ: R348.2 U83.H1(2Q7) ; also on sheet 15
MPC_2_CF_SP0_SS: U43.15(O0#) ; also on sheet 15
MPC_2_DISPLAY_SPI_SEL: U43.11(O4#) ; also on sheet 5
MPC_2_OB_SPI_SEL0: U43.14(O1#) ; also on sheet 6
MPC_2_OB_SPI_SEL1: U43.13(O2#) ; also on sheet 6
MPC_2_OB_SPI_SEL2: U43.12(O3#) ; also on sheet 6
MPC_CAN3_RX: R65.1 ; also on sheet 5 6
MPC_FEC1_COL: U1.Y18(FEC1_COL/GTM1_TIN1/GPIO_16/) ; also on sheet 7
MPC_FEC1_CRS: U1.AA19(FEC1_CRS/GTM1_TGATE1_B/GPIO_17) ; also on sheet 7
MPC_FEC1_RXCLK: U1.W16(FEC1_RX_CLK/GPIO_18/) ; also on sheet 7
MPC_FEC1_RXD0: U1.AB20(FEC1_RXD0/GPIO_21/JTAG_PRPGPS) ; also on sheet 7
MPC_FEC1_RXD1: U1.Y17(FEC1_RXD1/GTM1_TIN3/GPIO_22/JTAG_BISR__TDO_EN) ; also on sheet 7
MPC_FEC1_RXD2: U1.AB19(FEC1_RXD2/GTM1_TGATE3_B/GPIO_23/TPR_S_YS_AAD[0]) ; also on sheet 7
MPC_FEC1_RXD3: U1.AC21(FEC1_RXD3/GPIO_24/TPR_SYS_AAD[1]) ; also on sheet 7
MPC_FEC1_RXDV: U1.AC22(FEC1_RX_DV/GTM1_TIN2/GPIO_19/PLLCZ_CORE_CLKIN) ; also on sheet 7
MPC_FEC1_RXER: U1.AA18(FEC1_RX_ER/GTM1_TGATE2_B/GPIO_20/JTAG__BISE) ; also on sheet 7
MPC_FEC1_TXCLK: R159.2 ; also on sheet 7
MPC_FEC1_TXD0: R137.2 ; also on sheet 7
MPC_FEC1_TXD1: R139.2 ; also on sheet 7
MPC_FEC1_TXD2: R141.2 ; also on sheet 7
MPC_FEC1_TXD3: R144.2 ; also on sheet 7
MPC_FEC1_TXEN: R132.2 ; also on sheet 7
MPC_FEC1_TXER: R134.2
MPC_FEC2_COL: U1.Y15(FEC2_COL/GTM2_TIN1/GPIO_32/TPR_SYS_AA_D[9]) ; also on sheet 7
MPC_FEC2_CRS: U1.AC17(FEC2_CRS/GTM2_TGATE1_B/GPIO_33/TPR_SY_S_AAD[10]) ; also on sheet 7
MPC_FEC2_RXCLK: U1.W14(FEC2_RX_CLK/GPIO_34/TPR_SYS_AAD[11]) ; also on sheet 7
MPC_FEC2_RXD0: U1.AA15(FEC2_RXD0/GPIO_37/TPR_SYS_AAD[14]) ; also on sheet 7
MPC_FEC2_RXD1: U1.AC15(FEC2_RXD1/GTM2_TIN3/GPIO_38/TPR_SYS_A_AD[15]) ; also on sheet 7
MPC_FEC2_RXD2: U1.AC16(FEC2_RXD2/GTM2_TGATE3_B/GPIO_39/TPR_SYS_SYNC) ; also on sheet 7
MPC_FEC2_RXD3: U1.AA14(FEC2_RXD3/GPIO_40/TPR_SYS_DACK) ; also on sheet 7
MPC_FEC2_RXDV: U1.AB16(FEC2_RX_DV/GTM2_TIN2/GPIO_35/TPR_SYS__AAD[12]) ; also on sheet 7
MPC_FEC2_RXER: R157.1 U1.Y14(FEC2_RX_ER/GTM2_TGATE2_B/GPIO_36/TPR__SYS_AAD[13]) ; also on sheet 7
MPC_FEC2_TXCLK: R158.1 ; also on sheet 7
MPC_FEC2_TXD0: R146.1 ; also on sheet 7
MPC_FEC2_TXD1: R143.1 ; also on sheet 7
MPC_FEC2_TXD2: R140.1 ; also on sheet 7
MPC_FEC2_TXD3: R138.1 ; also on sheet 7
MPC_FEC2_TXEN: R148.1 ; also on sheet 7
MPC_FEC2_TXER: R147.1
MPC_FEC3_COL: U1.AC12(FEC3_COL/GPIO_48/) ; also on sheet 6
MPC_FEC3_CRS: U1.W11(FEC3_CRS/GPIO_49/) ; also on sheet 6
MPC_FEC3_RXCLK: U1.W12(FEC3_RX_CLK/GPIO_50/) ; also on sheet 6
MPC_FEC3_RXD0: U1.AA11(FEC3_RXD0/FEC3_TMR_TX_ESFD/GPIO_53/) ; also on sheet 6
MPC_FEC3_RXD1: U1.AC11(FEC3_RXD1/FEC3_TMR_RX_ESFD/GPIO_54/) ; also on sheet 6
MPC_FEC3_RXD2: U1.Y11(FEC3_RXD2/TSEC_TMR_TRIG1/GPIO_55/) ; also on sheet 6
MPC_FEC3_RXD3: U1.AB10(FEC3_RXD3/TSEC_TMR_TRIG2/GPIO_56/) ; also on sheet 6
MPC_FEC3_RXDV: U1.AA12(FEC3_RX_DV/FEC1_TMR_TX_ESFD/GPIO_51/) ; also on sheet 6
MPC_FEC3_RXER: R156.1 U1.AB11(FEC3_RX_ER/FEC1_TMR_RX_ESFD/GPIO_52/) ; also on sheet 6
MPC_FEC3_TXCLK: R342.2 ; also on sheet 6
MPC_FEC3_TXCLK\TMR_CLK: R151.1 R342.1 R343.1
MPC_FEC3_TXD0: R123.1 ; also on sheet 6
MPC_FEC3_TXD1: R126.1 ; also on sheet 6
MPC_FEC3_TXD2: R122.1 ; also on sheet 6
MPC_FEC3_TXD3: R125.1 ; also on sheet 6
MPC_FEC3_TXEN: R482.2 ; also on sheet 6
MPC_FEC3_TXEN\TMR_GCLK: R124.1 R482.1 R483.1
MPC_FEC3_TXER: R127.1 ; also on sheet 6
MPC_FEC_MDC: R149.2 R150.1 ; also on sheet 6 7
MPC_FEC_MDIO: R152.2 R153.1 ; also on sheet 6 7
MPC_HDLC1_CD#: R114.2 U1.W19(HDLC1_CD_B/GPIO_4/TDM1_TFS/) U14.4(O) ; also on sheet 6
MPC_HDLC1_CTS#: R254.1 U1.V19(HDLC1_CTS_B/GPIO_5/TDM1_RFS/) ; also on sheet 6
MPC_HDLC1_RCK: U1.AA21(HDLC1_RXCLK/GPIO_1/TDM1_RCK/) ; also on sheet 6
MPC_HDLC1_RTS#_BOOT_CFG1: U1.AA23(HDLC1_RTS_B/GPIO_6/TDM1_STROBE_B/CFG__RESET_SOURCE[1]) U47.1(I0) U47.2(I1) U49.1(Anode) U70.2(I1) ; also on sheet 6 8
MPC_HDLC1_RXD: R357.2 U1.AB23(HDLC1_RXD/GPIO_3/TDM1_RD/) U16.2(I) U31.4(RXD) ; also on sheet 6
MPC_HDLC1_TCK: U1.AA20(HDLC1_TXCLK/GPIO_0/QE_BRG_5/TDM1_TCK) U16.4(O) ; also on sheet 6
MPC_HDLC1_TXD_BOOT_CFG0: R356.1 U1.AB22(HDLC1_TXD/GPIO_2/TDM1_TD/CFG_RESET_S_OURCE[0]) U31.7(TXD) ; also on sheet 6 8
MPC_HDLC2_CD#: R115.2 U1.V20(HDLC2_CD_B/GPIO_20/TDM2_TFS/) U15.4(O) ; also on sheet 6
MPC_HDLC2_CTS#: R253.1 U1.Y23(HDLC2_CTS_B/GPIO_21/TDM2_RFS/) ; also on sheet 6
MPC_HDLC2_RCK: U1.Y22(HDLC2_RXCLK/GPIO_17/TDM2_RCK/QE_BRG__8) ; also on sheet 6
MPC_HDLC2_RTS#_BOOT_CFG3: U1.U20(HDLC2_RTS_B/GPIO_22/TDM2_STROBE_B/CF_G_RESET_SOURCE[3]) U48.1(I0) U48.2(I1) U52.1(Anode) U71.2(I1) ; also on sheet 6 8
MPC_HDLC2_RXD: R360.2 U1.W21(HDLC2_RXD/GPIO_19/TDM2_RD/) U20.2(I) U33.4(RXD) ; also on sheet 6
MPC_HDLC2_TCK: U1.Y20(HDLC2_TXCLK/GPIO_16/QE_BRG_7/TDM2_TCK) U20.4(O) ; also on sheet 6
MPC_HDLC2_TXD_BOOT_CFG2: R359.1 U1.W20(HDLC2_TXD/GPIO_18/TDM2_TD/CFG_RESET__SOURCE[2]) U33.7(TXD) ; also on sheet 6 8
MPC_I2C1_SCL: R85.1 U1.B20(IIC_SCL1) ; also on sheet 6
MPC_I2C1_SDA: R84.1 U1.A20(IIC_SDA1) ; also on sheet 6
MPC_I2C2_SCL: R87.1 U1.C20(IIC_SCL2/CKSTOP_IN_B/) ; also on sheet 2 5 6 15
MPC_I2C2_SDA: R86.1 U1.D19(IIC_SDA2_/CKSTOP_OUT_B/) ; also on sheet 2 5 6 15
MPC_IRQ0#: R45.2 R66.1 U1.A21(IRQ_B0_MCP_IN_B)
MPC_IRQ1#: R46.2 R61.1 U1.A22(IRQ_B1/MCP_OUT_B/)
MPC_IRQ2#: R47.2 R67.1 U1.E18(IRQ_B2/CKSTOP_IN_B/)
MPC_IRQ3#: R48.2 R69.1 U1.E19(IRQ_B3/CKSTOP_OUT_B/INTA_B/)
MPC_LALE: U1.A17(LALE) U82.A4(1LE) U82.J4(2LE)
MPC_LBC_ADD0: U82.A1(1Q1) ; also on sheet 6
MPC_LBC_ADD1: U82.B2(1Q2) ; also on sheet 6 10
MPC_LBC_ADD2: U82.B1(1Q3) ; also on sheet 6 10
MPC_LBC_ADD3: U82.C2(1Q4) ; also on sheet 6 10
MPC_LBC_ADD4: U82.C1(1Q5) ; also on sheet 6 10
MPC_LBC_ADD5: U82.D2(1Q6) ; also on sheet 6 10
MPC_LBC_ADD6: U82.D1(1Q7) ; also on sheet 6 10
MPC_LBC_ADD7: U82.E2(1Q8) ; also on sheet 6 10
MPC_LBC_ADD8: U82.E1(2Q1) ; also on sheet 6 10
MPC_LBC_ADD9: U82.F2(2Q2) ; also on sheet 6 10
MPC_LBC_ADD10: U82.F1(2Q3) ; also on sheet 6 10
MPC_LBC_ADD11: U82.G2(2Q4) ; also on sheet 6 10
MPC_LBC_ADD12: U82.G1(2Q5) ; also on sheet 6 10
MPC_LBC_ADD13: U82.H2(2Q6) ; also on sheet 6 10
MPC_LBC_ADD14: U82.H1(2Q7) ; also on sheet 6 10
MPC_LBC_ADD15: U82.J1(2Q8) ; also on sheet 6 10
MPC_LBC_ADD16: U1.C11(LA16) ; also on sheet 6 10
MPC_LBC_ADD17: U1.B10(LA17) ; also on sheet 6 10
MPC_LBC_ADD18: U1.D12(LA18) ; also on sheet 6 10
MPC_LBC_ADD19: U1.A9(LA19) ; also on sheet 6 10
MPC_LBC_ADD20: U1.E12(LA20) ; also on sheet 6 10
MPC_LBC_ADD21: U1.B11(LA21) ; also on sheet 6 10
MPC_LBC_ADD22: U1.A11(LA22) ; also on sheet 6 10
MPC_LBC_ADD23: U1.A10(LA23) ; also on sheet 6 10
MPC_LBC_ADD24: U1.C12(LA24) ; also on sheet 5 6 10
MPC_LBC_ADD25: U1.A12(LA25) ; also on sheet 6
MPC_LBC_ALE: U1.C15(LGPL1/LFALE) ; also on sheet 6
MPC_LBC_CLE: U1.C14(LGPL0/LFCLE) ; also on sheet 6
MPC_LBC_CS0#: R80.1 U1.D13(LCS_B0) ; also on sheet 6 8
MPC_LBC_CS1#: R81.1 U1.C13(LCS_B1) U30.2(I1) U45.1(I0) U46.1(I0)
MPC_LBC_CS2#: R82.1 U1.A13(LCS_B2) ; also on sheet 5
MPC_LBC_CS3#: R83.1 U1.B13(LCS_B3) ; also on sheet 6
MPC_LBC_D0: U84.A1(1B1) ; also on sheet 5 6
MPC_LBC_D1: U84.B2(1B2) ; also on sheet 5 6
MPC_LBC_D2: U84.B1(1B3) ; also on sheet 5 6
MPC_LBC_D3: U84.C2(1B4) ; also on sheet 5 6
MPC_LBC_D4: U84.C1(1B5) ; also on sheet 5 6
MPC_LBC_D5: U84.D2(1B6) ; also on sheet 5 6
MPC_LBC_D6: U84.D1(1B7) ; also on sheet 5 6
MPC_LBC_D7: U84.E2(1B8) ; also on sheet 5 6
MPC_LBC_D8: U84.E1(2B1) ; also on sheet 5
MPC_LBC_D9: U84.F2(2B2) ; also on sheet 5
MPC_LBC_D10: U84.F1(2B3) ; also on sheet 5
MPC_LBC_D11: U84.G2(2B4) ; also on sheet 5
MPC_LBC_D12: U84.G1(2B5) ; also on sheet 5
MPC_LBC_D13: U84.H2(2B6) ; also on sheet 5
MPC_LBC_D14: U84.H1(2B7) ; also on sheet 5
MPC_LBC_D15: U84.J1(2B8) ; also on sheet 5
MPC_LBC_GPL5: U1.B17(LGPL5) ; also on sheet 6
MPC_LBC_LAD0: U1.B5(LAD0) U82.A6(1D1) U83.A6(1D1) U84.A6(1A1) U85.A6(1A1) ; also on sheet 10
MPC_LBC_LAD1: U1.A4(LAD1) U82.B5(1D2) U83.B5(1D2) U84.B5(1A2) U85.B5(1A2) ; also on sheet 10
MPC_LBC_LAD2: U1.C7(LAD2) U82.B6(1D3) U83.B6(1D3) U84.B6(1A3) U85.B6(1A3) ; also on sheet 10
MPC_LBC_LAD3: U1.D9(LAD3) U82.C5(1D4) U83.C5(1D4) U84.C5(1A4) U85.C5(1A4) ; also on sheet 10
MPC_LBC_LAD4: U1.A5(LAD4) U82.C6(1D5) U83.C6(1D5) U84.C6(1A5) U85.C6(1A5) ; also on sheet 10
MPC_LBC_LAD5: U1.E10(LAD5) U82.D5(1D6) U83.D5(1D6) U84.D5(1A6) U85.D5(1A6) ; also on sheet 10
MPC_LBC_LAD6: U1.A6(LAD6) U82.D6(1D7) U83.D6(1D7) U84.D6(1A7) U85.D6(1A7) ; also on sheet 10
MPC_LBC_LAD7: U1.C8(LAD7) U82.E5(1D8) U83.E5(1D8) U84.E5(1A8) U85.E5(1A8) ; also on sheet 10
MPC_LBC_LAD8: U1.D10(LAD8) U82.E6(2D1) U83.E6(2D1) U84.E6(2A1) U85.E6(2A1) ; also on sheet 10
MPC_LBC_LAD9: U1.A7(LAD9) U82.F5(2D2) U83.F5(2D2) U84.F5(2A2) U85.F5(2A2) ; also on sheet 10
MPC_LBC_LAD10: U1.B7(LAD10) U82.F6(2D3) U83.F6(2D3) U84.F6(2A3) U85.F6(2A3) ; also on sheet 10
MPC_LBC_LAD11: U1.C9(LAD11) U82.G5(2D4) U83.G5(2D4) U84.G5(2A4) U85.G5(2A4) ; also on sheet 10
MPC_LBC_LAD12: U1.E11(LAD12) U82.G6(2D5) U83.G6(2D5) U84.G6(2A5) U85.G6(2A5) ; also on sheet 10
MPC_LBC_LAD13: U1.B8(LAD13) U82.H5(2D6) U83.H5(2D6) U84.H5(2A6) U85.H5(2A6) ; also on sheet 10
MPC_LBC_LAD14: U1.A8(LAD14) U82.H6(2D7) U83.H6(2D7) U84.H6(2A7) U85.H6(2A7) ; also on sheet 10
MPC_LBC_LAD15: U1.C10(LAD15) U82.J6(2D8) U83.J6(2D8) U84.J6(2A8) U85.J6(2A8) ; also on sheet 10
MPC_LBC_RB#: R79.1 U1.E14(LGPL4/LGTA_B/LUPWA) ; also on sheet 6
MPC_LBC_RE/OE#: R77.1 U1.B16(LGPL2/LOE_B/LFRE_B) U46.2(I1) ; also on sheet 6 10
MPC_LBC_WE0#: R75.1 U1.A14(LWE_B0/LFWE_B0/LBS_B0) U45.2(I1) ; also on sheet 5 6 10
MPC_LBC_WE1#: R76.1 U1.B14(LWE_B1/LBS_B1) ; also on sheet 6
MPC_LBC_WP#: R78.1 U1.A16(LGPL3/LFWP_B) ; also on sheet 6
MPC_LBCTL: U1.A15(LBCTL) U84.A3(1DIR) U84.J3(2DIR) ; also on sheet 6
MPC_LCK0: R13.1 R68.1 ; also on sheet 6
MPC_OB_SPI_CLK: R72.1 U1.E17(SPICLK) ; also on sheet 5 6 15
MPC_OB_SPI_MISO: R73.1 U1.E16(SPIMISO) ; also on sheet 5 6 15
MPC_OB_SPI_MOSI: R74.1 U1.B19(SPIMOSI) ; also on sheet 5 6 15
MPC_PCI_AD0: J9.96(AD[0]) U1.B23(PCI_AD0/BOOT_ROM_ADDR[2]) ; also on sheet 6
MPC_PCI_AD1: J9.99(AD[1]) U1.C21(PCI_AD1/BOOT_ROM_ADDR[3]) ; also on sheet 6
MPC_PCI_AD2: J9.94(AD[2]) U1.E20(PCI_AD2/BOOT_ROM_ADDR[4]) ; also on sheet 6
MPC_PCI_AD3: J9.95(AD[3]) U1.G19(PCI_AD3/BOOT_ROM_ADDR[5]) ; also on sheet 6
MPC_PCI_AD4: J9.92(AD[4]) U1.C23(PCI_AD4/BOOT_ROM_ADDR[6]) ; also on sheet 6
MPC_PCI_AD5: J9.91(AD[5]) U1.H19(PCI_AD5/BOOT_ROM_ADDR[7]) ; also on sheet 6
MPC_PCI_AD6: J9.90(AD[6]) U1.D21(PCI_AD6/CE_PIO_0/BOOT_ROM_ADDR[8]) ; also on sheet 6
MPC_PCI_AD7: J9.87(AD[7]) U1.F20(PCI_AD7BOOT_ROM_ADDR[9]) ; also on sheet 6
MPC_PCI_AD8: J9.85(AD[8]) U1.E21(PCI_AD8/TPR_SYS_AAD[0]/BOOT_ROM_ADDR[_10]) ; also on sheet 6
MPC_PCI_AD9: J9.84(AD[9]) U1.H20(PCI_AD9/TPR_SYS_AAD[1]/BOOT_ROM_ADDR[_11]) ; also on sheet 6
MPC_PCI_AD10: J9.81(AD[10]) U1.D22(PCI_AD10/TPR_SYS_AAD[2]/BOOT_ROM_ADDR_[12]) ; also on sheet 6
MPC_PCI_AD11: J9.80(AD[11]) U1.D23(PCI_AD11/TPR_SYS_AAD[3]/BOOT_ROM_RDAT_A[0]) ; also on sheet 6
MPC_PCI_AD12: J9.79(AD[12]) U1.J19(PCI_AD12/TPR_SYS_AAD[4]/BOOT_ROM_RDAT_A[1]) ; also on sheet 6
MPC_PCI_AD13: J9.78(AD[13]) U1.F21(PCI_AD13/TPR_SYS_AAD[5]/BOOT_ROM_RDAT_A[2]) ; also on sheet 6
MPC_PCI_AD14: J9.75(AD[14]) U1.G21(PCI_AD14/TPR_SYS_AAD[6]/BOOT_ROM_RDAT_A[3]) ; also on sheet 6
MPC_PCI_AD15: J9.76(AD[15]) U1.E22(PCI_AD15/TPR_SYS_AAD[7]/BOOT_ROM_RDAT__A[4]) ; also on sheet 6
MPC_PCI_AD16: J9.60(AD[16]) U1.E23(PCI_AD16/TPR_SYS_AAD[8]/BOOT_ROM_RDAT_A[5]) ; also on sheet 6
MPC_PCI_AD17: J9.57(AD[17]) U1.J20(PCI_AD17/TPR_SYS_AAD[9]/BOOT_ROM_RDAT_A[6]) ; also on sheet 6
MPC_PCI_AD18: J9.58(AD[18]) R293.2 U1.F23(PCI_AD18/TPR_SYS_AAD[10]/BOOT_ROM_RDA_TA[7]) ; also on sheet 6
MPC_PCI_AD19: J9.53(AD[19]) U1.G23(PCI_AD19/TPR_SYS_AAD[11]/BOOT_ROM_RDA_TA[8]) ; also on sheet 6
MPC_PCI_AD20: J9.54(AD[20]) U1.K19(PCI_AD20/TPR_SYS_AAD[12]/BOOT_ROM_RDA_TA[9]) ; also on sheet 6
MPC_PCI_AD21: J9.51(AD[21]) U1.H21(PCI_AD21/TPR_SYS_AAD[13]/BOOT_ROM_RDA_TA[10]) ; also on sheet 6
MPC_PCI_AD22: J9.52(AD[22]) U1.L19(PCI_AD22/TPR_SYS_AAD[14]/BOOT_ROM_RDA_TA[11]) ; also on sheet 6
MPC_PCI_AD23: J9.47(AD[23]) U1.G22(PCI_AD23/TPR_SYS_AAD[15]/BOOT_ROM_RDA_TA[12]) ; also on sheet 6
MPC_PCI_AD24: J9.46(AD[24]) U1.H23(PCI_AD24/TPR_SYS_SYNC/BOOT_ROM_RDATA_[13]) ; also on sheet 6
MPC_PCI_AD25: J9.41(AD[25]) U1.J21(PCI_AD25/TPR_SYS_DACK/BOOT_ROM_RDATA_[14]) ; also on sheet 6
MPC_PCI_AD26: J9.44(AD[26]) U1.H22(PCI_AD26/UC5_URM/BOOT_ROM_RDATA[15]) ; also on sheet 6
MPC_PCI_AD27: J9.39(AD[27]) U1.J23(PCI_AD27BOOT_ROM_RDATA[16]) ; also on sheet 6
MPC_PCI_AD28: J9.42(AD[28]) U1.K18(PCI_AD28/UC7_URM/BOOT_ROM_RDATA[17]) ; also on sheet 6
MPC_PCI_AD29: J9.35(AD[29]) U1.K21(PCI_AD29BOOT_ROM_RDATA[18]) ; also on sheet 6
MPC_PCI_AD30: J9.38(AD[30]) U1.K22(PCI_AD30BOOT_ROM_RDATA[19]) ; also on sheet 6
MPC_PCI_AD31: J9.33(AD[31]) U1.K23(PCI_AD31BOOT_ROM_RDATA[20]) ; also on sheet 6
MPC_PCI_CBE0#: J9.86(C/BE[0]#) R268.1 U1.L20(PCI_C_BE_B0_/_BOOT_ROM_RDATA[21]) ; also on sheet 6
MPC_PCI_CBE1#: J9.73(C/BE[1]#) R269.1 U1.L23(PCI_C_BE_B1_/_BOOT_ROM_RDATA[22]) ; also on sheet 6
MPC_PCI_CBE2#: J9.59(C/BE[2]#) R270.1 U1.L22(PCI_C_BE_B2_/_BOOT_ROM_RDATA[23]) ; also on sheet 6
MPC_PCI_CBE3#: J9.45(C/BE[3]#) R271.1 U1.L21(PCI_C_BE_B3_/_SYSTEM_PLL_OUT/BOOT_ROM_RDATA[24]) ; also on sheet 6
MPC_PCI_CLK0: J9.25(CLK) R288.2 ; also on sheet 6
MPC_PCI_CLK1: R289.2 ; also on sheet 6
MPC_PCI_CLK2: R290.2 ; also on sheet 6
MPC_PCI_CLKRUN#: J9.65(CLKRUN#) R295.2
MPC_PCI_DEVSEL#: J9.72(DEVSEL#) R277.1 U1.N22(PCI_DEVSEL_B_/_BOOT_ROM_RDATA[30]) ; also on sheet 6
MPC_PCI_FRAME#: J9.64(FRAME#) R273.1 U1.M20(PCI_FRAME_B_/_BOOT_ROM_RDATA[26]) ; also on sheet 6
MPC_PCI_GNT0#: J9.30(GNT#) R283.1 U1.T21(PCI_GNT_B0) ; also on sheet 6
MPC_PCI_GNT1#: R284.1 U1.U22(PCI_GNT_B1/CPCI_HS_LED/_PCI_GNT_B0) ; also on sheet 6
MPC_PCI_GNT2#: R285.1 U1.U21(PCI_GNT_B2/CPCI_HS_ENUM/) ; also on sheet 6
MPC_PCI_IDSEL#: R287.1 U1.N21(PCI_IDSEL_/_BOOT_ROM_RDATA[31]) ; also on sheet 6
MPC_PCI_INTA#: J9.20(INTA#) R57.2 R266.1 U1.B22(PCI_INTA_B) U13.5(I1) ; also on sheet 6
MPC_PCI_IRDY#: J9.61(IRDY#) R275.1 U1.M21(PCI_IRDY_B_/_BOOT_ROM_RDATA[28]) ; also on sheet 6
MPC_PCI_M66EN: J9.104(M66EN) R286.1 U1.V21(M66EN) ; also on sheet 6
MPC_PCI_PAR: J9.56(PAR) R272.1 U1.M19(PCI_PAR/QE_PLL_OUT/BOOT_ROM_RDATA[25]) ; also on sheet 6
MPC_PCI_PERR#: J9.71(PERR#) R279.1 U1.P20(PCI_PERR_B_/_BOOT_ROM_RWB) ; also on sheet 6
MPC_PCI_PME#: J9.34(PME#) R294.1
MPC_PCI_REQ0#: J9.29(REQ#) R280.1 U1.P21(PCI_REQ_B0_/_BOOT_ROM_XFR_WAIT) ; also on sheet 6
MPC_PCI_REQ1#: R281.1 U1.P22(PCI_REQ_B1/CPCI_HS_ES/BOOT_ROM_XFR_E_RR) ; also on sheet 6
MPC_PCI_REQ2#: R282.1 U1.T22(PCI_REQ_B2) ; also on sheet 6
MPC_PCI_RST_OUT#: J9.26(RST#) R267.1 U1.F19(PCI_RESET_OUT_B) ; also on sheet 6
MPC_PCI_SERR#: J9.67(SERR#) R278.1 U1.N19(PCI_SERR_B_/_BOOT_ROM_MOD_EN) ; also on sheet 6
MPC_PCI_STOP#: J9.68(STOP#) R276.1 U1.N23(PCI_STOP_B_/_BOOT_ROM_RDATA[29]) ; also on sheet 6
MPC_PCI_SYNC_IN: R296.1 ; also on sheet 6
MPC_PCI_TRDY#: J9.66(TRDY#) R274.1 U1.M23(PCI_TRDY_B_/_BOOT_ROM_RDATA[27]) ; also on sheet 6
MPC_RST_TWR#: U83.J1(2Q8) ; also on sheet 5
MPC_SPI_SEL: R70.1 U1.A19(SPISEL)
MPC_SPI_SEL0: R391.2 U43.1(A0) U83.E1(2Q1)
MPC_SPI_SEL1: R387.2 U43.2(A1) U83.F2(2Q2)
MPC_SPI_SEL2: R349.2 U43.3(A2) U83.F1(2Q3)
MPC_SPI_SEL_BOOT#: R88.1 U1.D18(SPISEL_BOOT_B) ; also on sheet 6
MPC_TMR_CLK: R343.2 ; also on sheet 8
MPC_TMR_GCLK: R483.2 TP19.1(TP) ; also on sheet 2 15
MPC_UART1_CTS#: U1.Y9(UART1_SIN2/UART1_CTS_B1/) U81.7(1D)
MPC_UART1_RTS#: U1.W10(UART1_SOUT2/UART1_RTS_B1/) U81.9(2D)
MPC_UART1_RXD: U1.AC6(UART1_SIN1) U80.7(1D)
MPC_UART1_TXD: U1.AB7(UART1_SOUT1) U80.9(2D)
MPR121_2_MPC_IRQ#: R52.2 U11.1(I0) U85.G1(2B5) ; also on sheet 5
NOR_FLASH_CS#: U30.1(I0) ; also on sheet 8 10
OB_2_MPC_CF_SPI_IRQ#: R63.2 U79.2(I1) U85.H1(2B7) ; also on sheet 6
OB_2_MPC_I2C_IRQ#: R58.2 U79.9(I0) U85.J1(2B8) ; also on sheet 6
OB_2_MPC_SPI0_IRQ#: R59.2 U79.10(I1) U85.E1(2B1) ; also on sheet 6
OB_2_MPC_SPI1_IRQ#: R60.2 U79.5(I1) U85.F2(2B2) ; also on sheet 6
OB_2_MPC_SPI2_IRQ#: R62.2 U79.1(I0) U85.F1(2B3) ; also on sheet 6
OB_BOOT: R373.2 S3.8(SW8a) U85.E2(1B8) ; also on sheet 8
OBSEL: R371.2 S3.3(SW3a) U85.B1(1B3) ; also on sheet 15
PCI_SYNC_IN: R291.1 R296.2 U1.T23(PCI_SYNC_IN)
PCI_SYNC_OUT: R291.2 U1.R20(PCI_SYNC_OUT)
PHY_UART_CTS#: R353.2 U53.9(R2-OUT) U81.6(1S1)
PHY_UART_RTS#: R352.2 U53.10(T2-IN) U81.10(2S1)
PHY_UART_RXD: U53.12(R1-OUT) U80.6(1S1)
PHY_UART_TXD: U53.11(T1-IN) U80.10(2S1)
READ: U46.4(O) U85.A4(\~{1O}E) U85.J4(\~{2O}E)
RS232_CTS: J7.4 U53.8(R2-IN)
RS232_RTS: J7.3 U53.7(T2-OUT)
RS232_RXD: J7.2 U53.13(R1-IN)
RS232_TXD: J7.1 U53.14(T1-OUT)
RS485_1_DE: U31.6(DE) U54.4(O)
RS485_1_RE#: U14.1(OE) U16.1(OE) U31.5(RE#) U55.4(O)
RS485_2_DE: U33.6(DE) U57.4(O)
RS485_2_RE#: U15.1(OE) U20.1(OE) U33.5(RE#) U56.4(O)
RS485_EN1: R372.2 S3.4(SW4a) U54.2(I1) U55.1(I0) U55.2(I1) U85.C2(1B4)
RS485_EN2: R243.2 S3.5(SW5a) U56.1(I0) U56.2(I1) U57.2(I1) U85.C1(1B5)
SW0: R248.2 S3.6(SW6a) U85.D2(1B6)
SW1: R369.2 S3.7(SW7a) U85.D1(1B7)
SWPB_2_MPC_IRQ#: R55.2 U13.2(I1) ; also on sheet 8
TEP_UART1_CTS#: U81.3(1S4) U81.5(1S2) ; also on sheet 6
TEP_UART1_RTS#: U81.11(2S2) U81.13(2S4) ; also on sheet 6
TEP_UART1_RXD: U80.11(2S2) ; also on sheet 6
TEP_UART1_TXD: U80.5(1S2) ; also on sheet 6
UART-C1+: C305.1 U53.3(C1-)
UART-C2+: C311.1 U53.4(C2+)
UART-C2-: C311.2 U53.5(C2-)
UART-V+: C310.1 U53.2(V+)
UART-V-: C307.1 U53.6(V-)
UART_SEL0: R370.2 S3.1(SW1a) U80.2(1N2) U81.2(1N2) U85.A1(1B1)
UART_SEL1: R234.2 S3.2(SW2a) U80.14(IN1) U81.14(IN1) U85.B2(1B2)
USB_INT#: R64.2 U13.10(I1) ; also on sheet 9
VISO1: C233.1 C288.1 C289.1 C292.2 C303.1 J21.4 R358.2 U31.12(VISO_OUT) U31.19(VISO_IN) U50.1(I0) U50.5(VCC)
VISO2: C293.1 C294.1 C295.1 C296.2 C304.1 J20.4 R374.2 U33.12(VISO_OUT) U33.19(VISO_IN) U51.1(I0) U51.5(VCC)
WRITE: U45.4(O) U83.A4(1LE) U83.J4(2LE)
N19114523: R126.2 U1.AA9(FEC3_TXD1/TSEC_TMR_PP3/GPIO_61/)
N19114525: R123.2 U1.AB8(FEC3_TXD0/TSEC_TMR_PP2/GPIO_60/)
N19114543: R127.2 U1.AC8(FEC3_TX_ER/TSEC_TMR_PP1/GPIO_59/)
N19114545: R124.2 U1.AA10(FEC3_TX_EN/TSEC_TMR_GCLK/GPIO_58/)
N19114606: R125.2 U1.AC7(FEC3_TXD3/TSEC_TMR_ALARM2/GPIO_63/)
N19114665: R122.2 U1.AA8(FEC3_TXD2/TSEC_TMR_ALARM1/GPIO_62/)
N19114677: R143.2 U1.AA13(FEC2_TXD1/GTM2_TOUT2_B/GPIO_45/)
N19114679: R146.2 U1.Y12(FEC2_TXD0/GTM2_TOUT1_B/GPIO_44/PD_XLB_2MG_DDR_CLOCK)
N19114687: R147.2 U1.AC14(FEC2_TX_ER/GTM2_TOUT4_B/GPIO_43/)
N19114689: R148.2 U1.AB14(FEC2_TX_EN/GTM2_TGATE4_B/GPIO_42/CLOC_K_XLB_CLOCK_OUT)
N19114700: R138.2 U1.AC13(FEC2_TXD3/GPIO_47/)
N19114702: R140.2 U1.AB13(FEC2_TXD2/GTM2_TOUT3_B/GPIO_46/)
N19114785: R152.1 U1.W17(FEC_MDIO)
N19114806: R132.1 U1.AC19(FEC1_TX_EN/GTM1_TGATE4_B/GPIO_26/TPR__SYS_AAD[3])
N19114808: R134.1 U1.AC20(FEC1_TX_ER/GTM1_TOUT4_B/GPIO_27/TPR_S_YS_AAD[4])
N19114810: R144.1 U1.AB17(FEC1_TXD3/GPIO_31/TPR_SYS_AAD[8])
N19114812: R141.1 U1.AA16(FEC1_TXD2/GTM1_TOUT3_B/GPIO_30/TPR_SY_S_AAD[7])
N19114814: R139.1 U1.AC18(FEC1_TXD1/GTM1_TOUT2_B/GPIO_29/TPR_SY_S_AAD[6])
N19114816: R137.1 U1.AA17(FEC1_TXD0/GTM1_TOUT1_B/GPIO_28/TPR_SY_S_AAD[5])
N19114842: R149.1 U1.W18(FEC_MDC)
N19203154: R290.1 U1.R19(PCI_CLK2)
N19203832: R288.1 U1.T19(PCI_CLK0)
N19203895: R289.1 U1.U19(PCI_CLK1)
N21006008: J9.48(IDSEL) R293.1
N28240508: R358.1 U49.4(Emitter) U50.2(I1)
N28284122: R374.1 U51.2(I1) U52.4(Emitter)
N29212095: U48.4(O) U57.1(I0)
N32963463: R13.2 U1.E13(LCLK0)
N33887496: R66.2 U11.11(O)
N33887632: U11.6(O) U11.9(I0)
N33887683: U11.3(O) U11.12(I0)
N33887898: R61.2 U11.8(O)
N34511976: U14.2(I) U70.4(O)
N34578141: U15.2(I) U71.4(O)
N35628094: U47.4(O) U54.1(I0)
N37811646: R67.2 U13.11(O)
N37819859: U11.13(I1) U13.3(O)
N37847596: R69.2 U13.6(O)
N37879796: U13.12(I0) U79.6(O)
N37882277: U13.8(O) U13.13(I1)
N37884176: U79.4(I0) U79.8(O)
N37887978: U13.9(I0) U79.3(O)
N41093720: D11.1(ANODE) R362.1
N41093832: D13.1(ANODE) R363.1
N41093858: D12.1(ANODE) R364.1
N41094084: D10.1(ANODE) R361.1
N41094137: D15.1(ANODE) R365.1
N41094173: D17.1(ANODE) R367.1
N41094199: D16.1(ANODE) R368.1
N41094217: D14.1(ANODE) R366.1
N41370202: C5.2 FB3.1 U3.7(VDD) U3.8(OE)
N41370222: R20.2 R91.1
N41370228: R65.2 R68.2 R91.2 U3.1(ICLK)
N41370230: R24.1 U3.2(Q1)
N41370300: C6.1 FB4.1 OSC3.4(VCC) R19.2
N41370328: OSC3.1(TRI_STATE) R19.1
N41370378: OSC3.3(OUT) R20.1
N41370380: R22.1 U3.4(Q3)
N41370382: R23.1 U3.5(Q4)
N41370436: R28.1 U3.3(Q2)
N41553314: C305.2 U53.1(C1+)
N41558324: J7.6 R355.1 R459.1
N42094900: R38.1 U43.6(E3)
N42094973: R39.1 U43.4(E1#) U43.5(E2#)
N45045152: R151.2 U1.AC10(FEC3_TX_CLK/TSEC_TMR_CLK/GPIO_57/)
N45050624: R158.2 U1.W13(FEC2_TX_CLK/GTM2_TIN4/GPIO_41/)
N45053443: R159.1 U1.W15(FEC1_TX_CLK/GTM1_TIN4/GPIO_25/TPR_SYS__AAD[2])
N45551594: R380.2 U49.2(Cathode)
N45556808: R381.2 U52.2(Cathode)
N45684756: J9.24(3.3VAUX) R292.1

Not connected (* = marked no-connect by the designer): J9 1(TIP)* 2(RING)* 3(8PMJ-3)* 4(8PMJ-1)* 5(8PMJ-6)* 6(8PMJ-2)* 7(8PMJ-7)* 8(8PMJ-4)* 9(8PMJ-8)* 10(8PMJ-5)* 11(LED1_GRNP)* 12(LEDS_YELP)* 13(LED1_GRNN)* 14(LED2_YELN)* 15(CHSGND)* 16(RESERVED)* 17(INTB#)* 21(RESERVED)* 22(RESERVED)* 36(RESERVED)* 43(RESERVED)* 93(RESERVED)* 98(RESERVED_WIP)* 100(RESERVED_WIP)* 103(AC_SYNC)* 105(AC_SDATA_IN)* 106(AC_SDATA_OUT)* 107(AC_BIT_CLK)* 108(AC_CODEC_ID0#)* 109(AC_CODEC_ID1#)* 110(AC_RESET#)* 111(MOD_AUDIO_MON)* 112(RESERVED)* 113(AUDIO_GND)* 115(SYS_AUDIO_OUT)* 116(SYS_AUDIO_IN)* 117(SYS_AUDIO_OUT_GND)* 118(SYS_AUDIO_IN_GND)* 119(AUDIO_GND)* 120(AUDIO_GND)* 121(RESERVED)* 122(MPCIACT#)* 123(VCC5VA)* 124(3.3VAUX)* 125(ARM1)* 126(ARM2)*; J20 5; J21 5*; R22 2; U43 7(O7#)* 9(O6#)* 10(O5#)*; U79 11(O); U82 A2(NC3)* A5(NC1)* B3(NC4)* B4(NC2)* H3(NC4)* H4(NC2)* J2(NC3)* J5(NC1)*; U83 A2(NC3)* A5(NC1)* B3(NC4)* B4(NC2)* G2(2Q4) H3(NC4)* H4(NC2)* J2(NC3)* J5(NC1)*; U84 A2(NC3)* A5(NC1)* B3(NC4)* B4(NC2)* H3(NC4)* H4(NC1)* J2(NC3)* J5(NC2)*; U85 A2(NC3)* A5(NC1)* B3(NC4)* B4(NC2)* H3(NC4)* H4(NC1)* J2(NC3)* J5(NC2)*

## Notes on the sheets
sheet 11
- MPC PCI Interface
- Mini PCI Type3 Connector
- IDSEL <= AD18
  INTA <=MPC8309_IRQ3
  INTB<=NC
  INTC<=NC
  INTD<=NC
  PCICLK0
  PCIGNT1/PCIREQ1
- TO BE PLACED NEAR MINI PCI CONNECTOR
sheet 12
- RS232 PHY
- Quad 4:1 mux
- MPC - HDLC
- EN#   IN2   IN1   D to S
  0     0      0    D=S1
  0     0      1    D=S2
  0     1      0    D=S3
  0     1      1    D=S4
  1     X      X    OFF
- UCC5 & UCC7 - RS485
sheet 13
- MPC eLBC
- Latches
- Buffers
- Close to TX side
- I2C2 Address
  1. SGTL5000 = 0x0A
  2. MMA8541 = 0x1C
  3. MPR121 on Display Module = 0x5B
  (ADDR pin = VDD)
- MPC Interrupt
- SPI Routing Decode
sheet 14
- MPC FEC1,FEC2 & FEC3
